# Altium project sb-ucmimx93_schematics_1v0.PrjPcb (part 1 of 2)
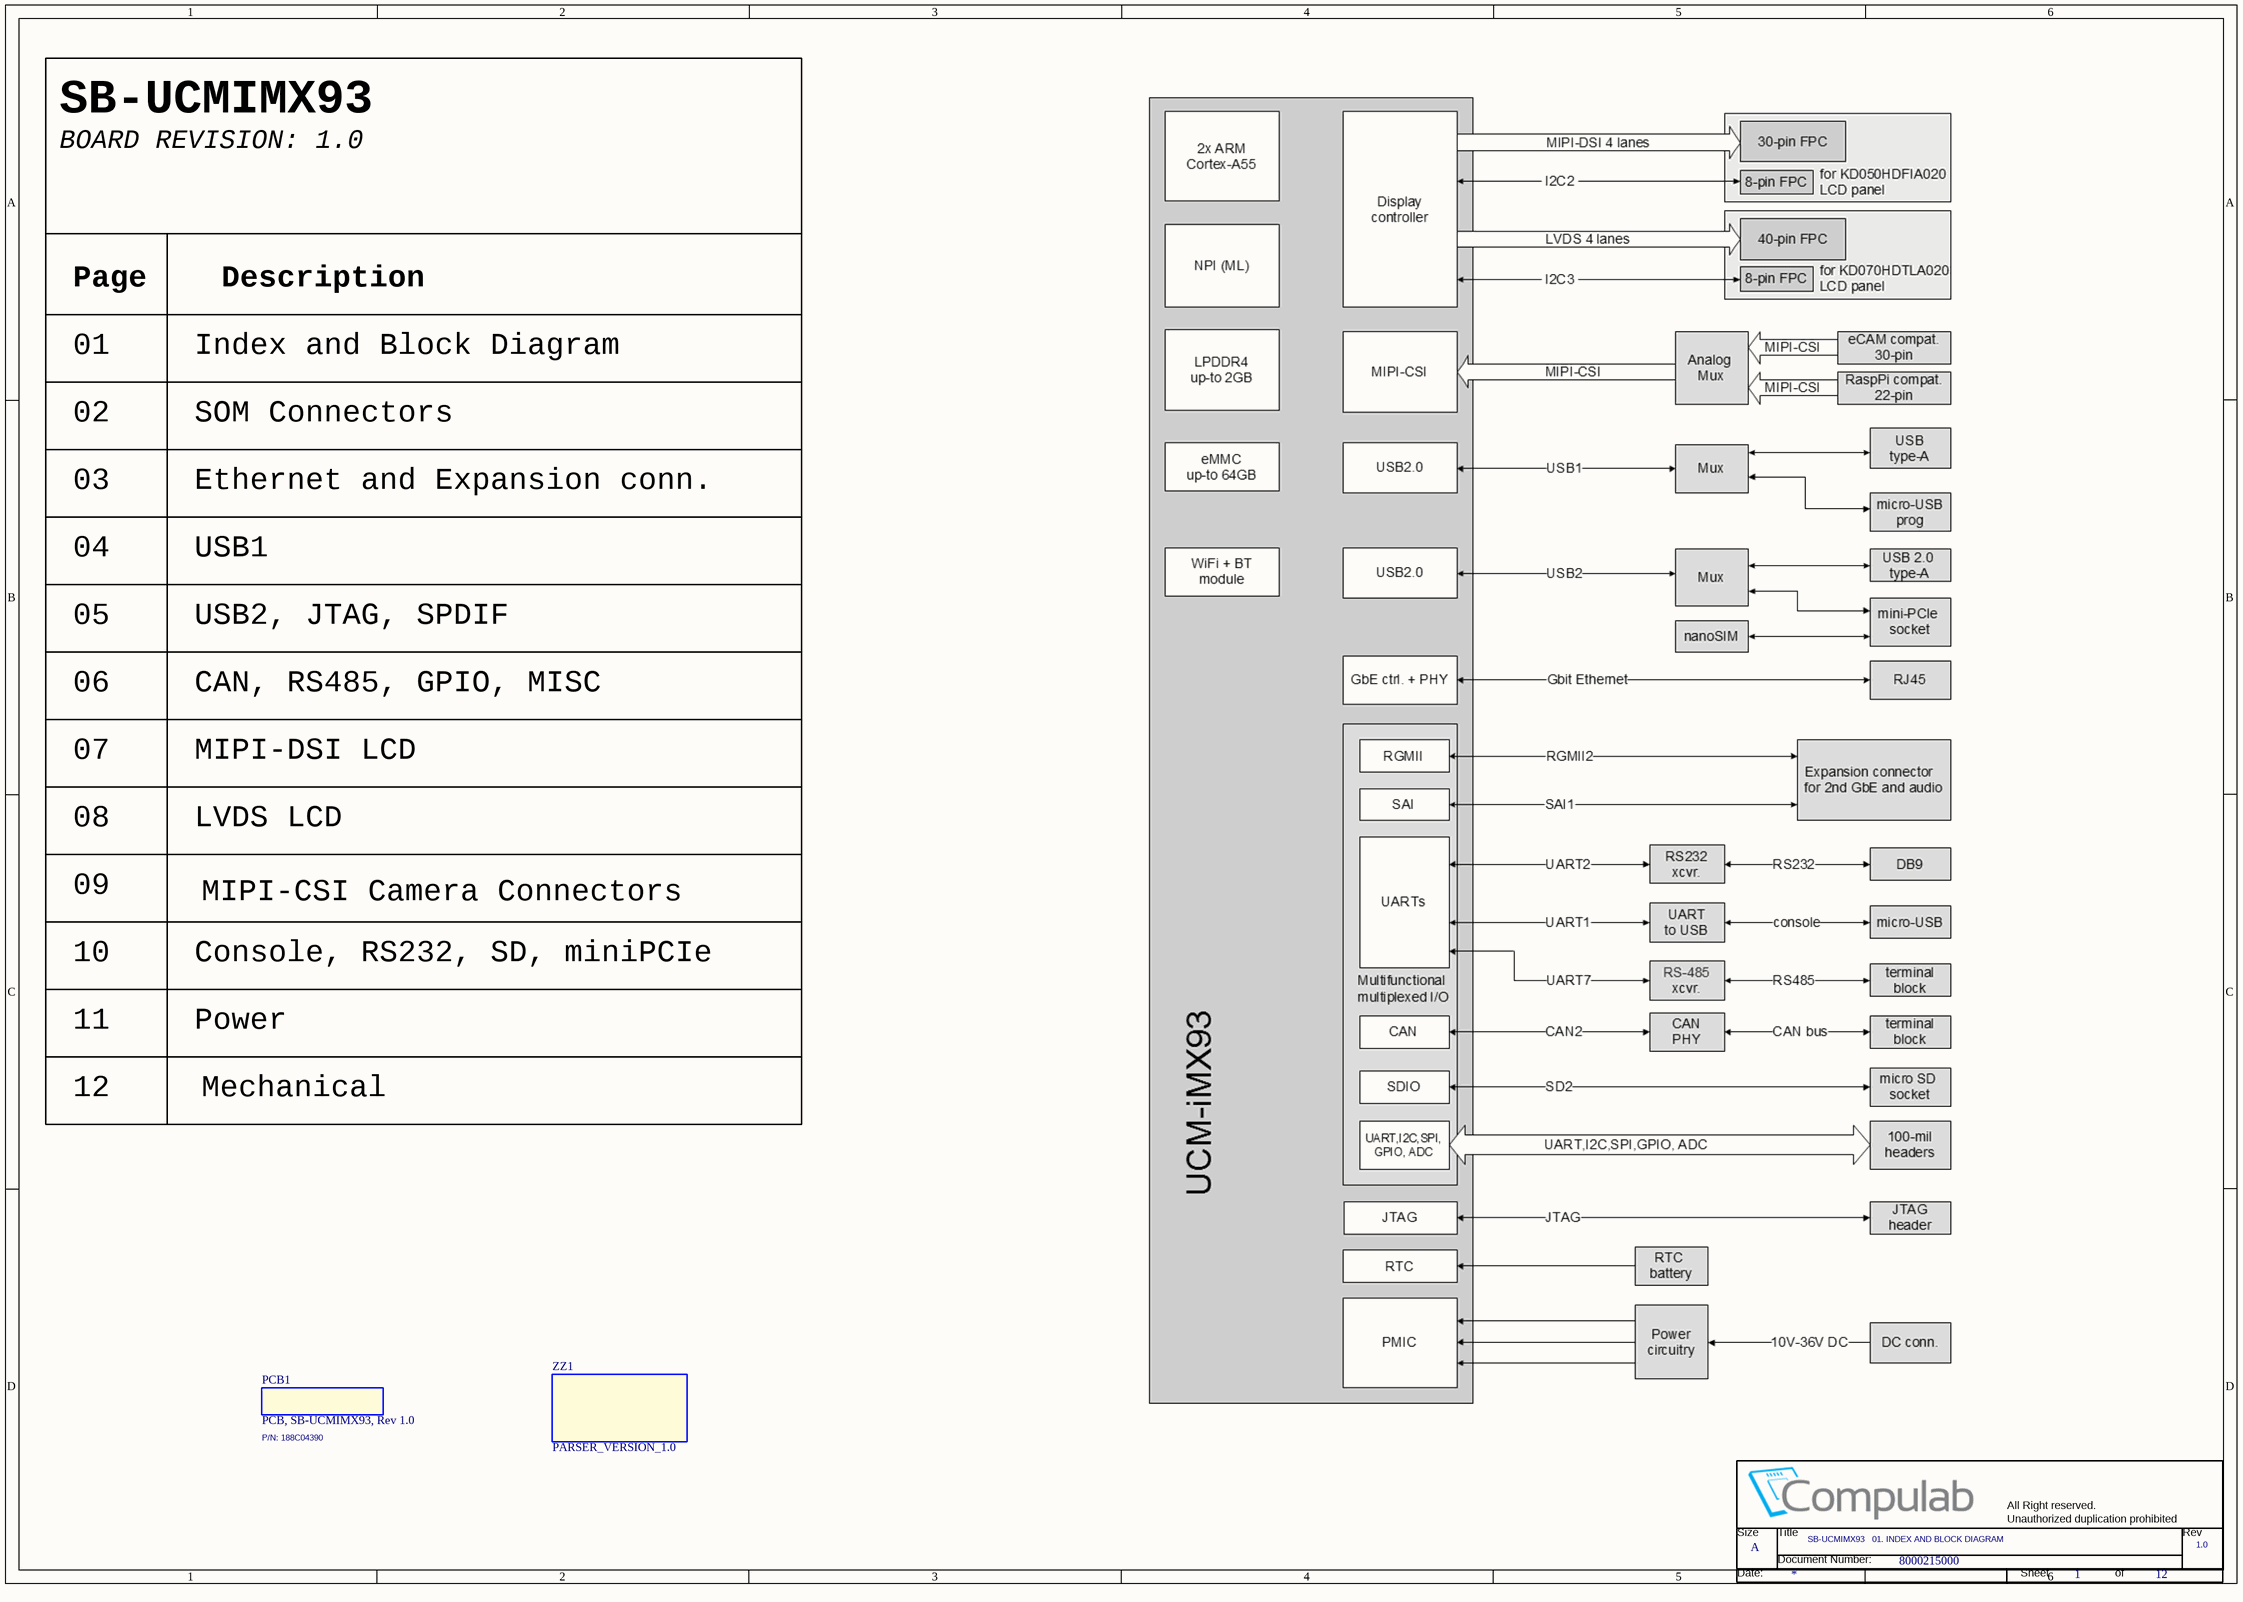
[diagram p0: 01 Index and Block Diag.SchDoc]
12 sheets, 492 parts. Net scope: flat (ports and power ports of the same name join across sheets).
Sheets:
  01 Index and Block Diag.SchDoc
  02 SOM Connectors.SchDoc
  03 Ethernet and Expansi.SchDoc
  04 USB1.SchDoc
  05 USB2, JTAG, SPDIF.SchDoc
  06 CAN, RS485, GPIO, MI.SchDoc
  07 MIPI-DSI LCD.SchDoc
  08 LVDS LCD.SchDoc
  09 MIPI-CSI Camera Conn.SchDoc
  10 Console, RS232, SD, .SchDoc
  11 Power.SchDoc
  12 Mechanical.SchDoc

## Sheet 01 Index and Block Diag.SchDoc
size 420 x 297 mm; DocumentNumber: 1; SheetNumber: 1; SheetTotal: 12

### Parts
(Parts that share a designator on the sheet are numbered #1, #2 ... from top to bottom, then left to right.)
*#1  Title: SB-UCMIMX93   01. INDEX AND BLOCK DIAGRAM  Doc: 8000215000  RevCode: 1.0  Page Size: A  Page Number: 1  Page Count: 12  (hidden comment: CompuLabTitleBlk)  (graphical)
PCB1  PCB, SB-UCMIMX93, Rev 1.0  P/N: 188C04390  [1X2THHDR]  (mechanical)
ZZ1  PARSER_VERSION_1.0  [1X2THHDR]  (mechanical)

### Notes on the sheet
- SB-UCMIMX93
- BOARD REVISION: 1.0
- Page
- Description
- 01
- Index and Block Diagram
- 02
- SOM Connectors
- 03
- Ethernet and Expansion conn.
- 04
- USB1
- 05
- USB2, JTAG, SPDIF
- 06
- CAN, RS485, GPIO, MISC
- 07
- MIPI-DSI LCD
- 08
- LVDS LCD
- 09
- MIPI-CSI Camera Connectors
- 10
- Console, RS232, SD, miniPCIe
- 11
- Power
- 12
- Mechanical

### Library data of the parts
PCB1 = PCB, EM-X270 Rev 1_0.1
ZZ1 = PARSER VERSION 1_1.0: P/N: 188Z10030; CLABCONF0: DNP

## Sheet 02 SOM Connectors.SchDoc
size 420 x 297 mm; DocumentNumber: 2; SheetNumber: 2; SheetTotal: 12
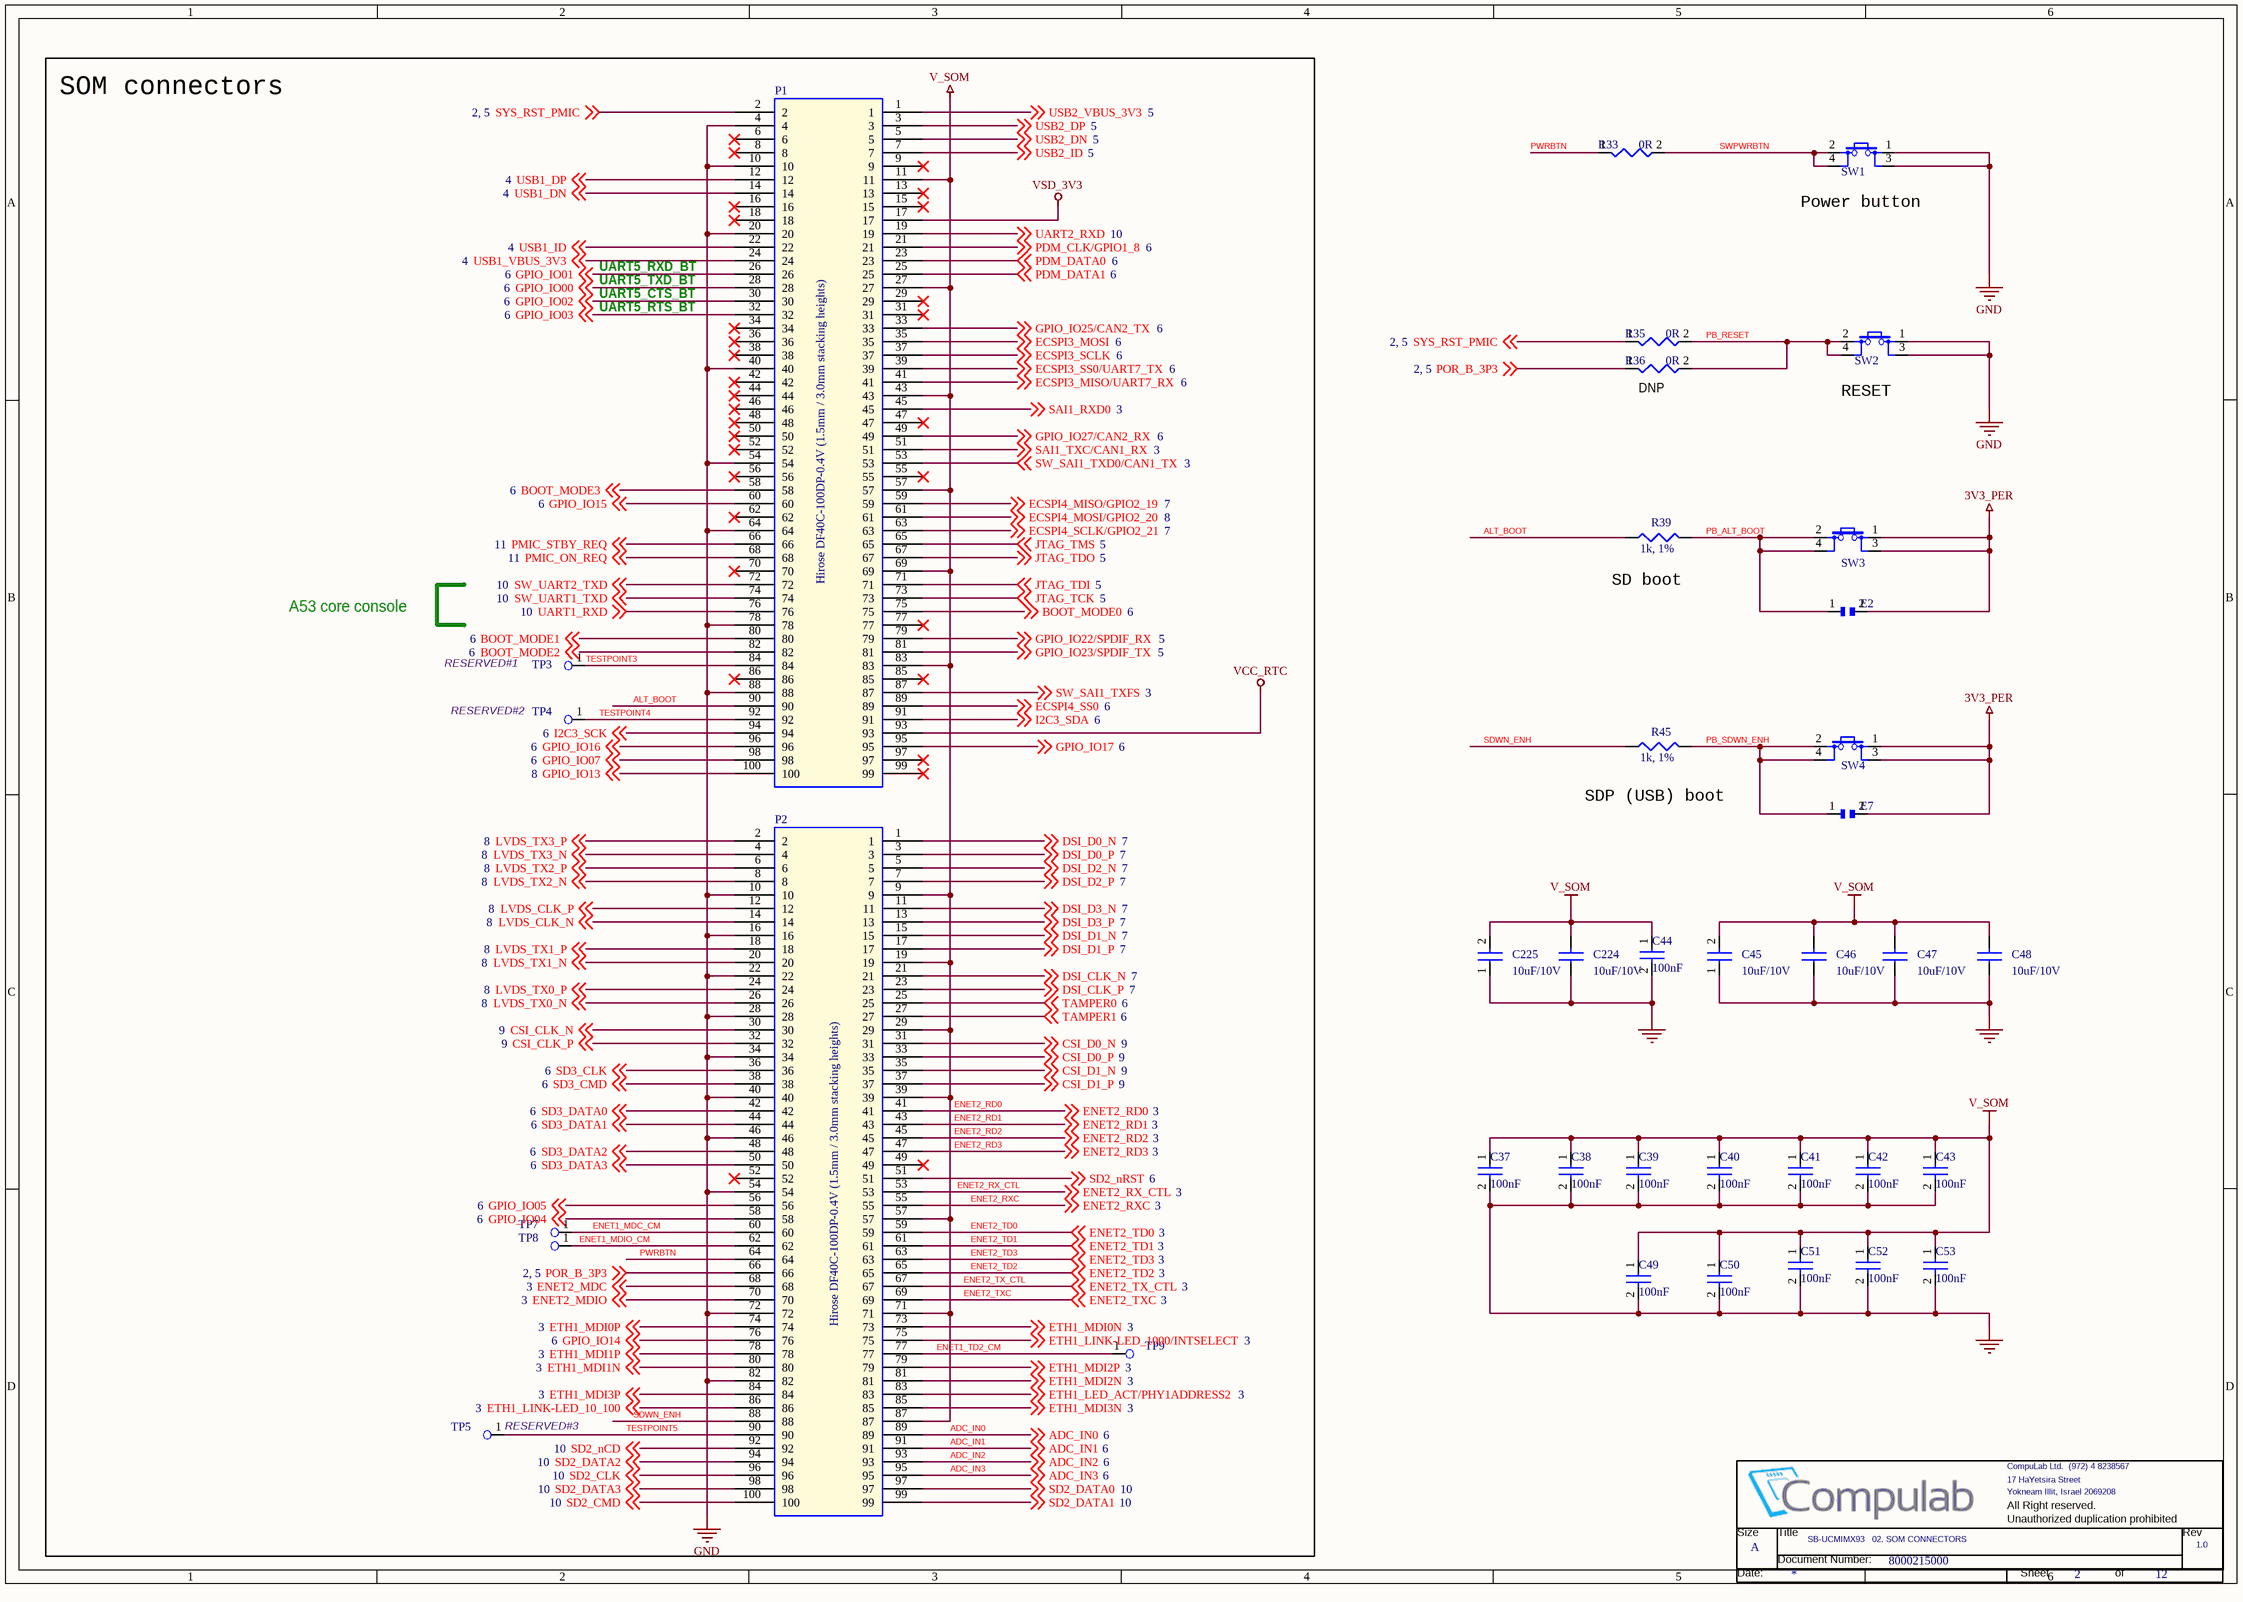
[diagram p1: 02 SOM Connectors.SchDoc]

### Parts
(Parts that share a designator on the sheet are numbered #1, #2 ... from top to bottom, then left to right.)
*#2  Title: SB-UCMIMX93   02. SOM CONNECTORS  Doc: 8000215000  RevCode: 1.0  OrgName: CompuLab Ltd.  (972) 4 8238567  OrgAddr1: 17 HaYetsira Street  OrgAddr2: Yokneam Illit, Israel 2069208  Page Size: A  Page Number: 2  Page Count: 12  (hidden comment: CompuLabTitleBlk)  (graphical)
C37  100nF  [RC0402]
C38  100nF  [RC0402]
C39  100nF  [RC0402]
C40  100nF  [RC0402]
C41  100nF  [RC0402]
C42  100nF  [RC0402]
C43  100nF  [RC0402]
C44  100nF  [RC0402]
C45  10uF/10V  [0402]
C46  10uF/10V  [0402]
C47  10uF/10V  [0402]
C48  10uF/10V  [0402]
C49  100nF  [RC0402]
C50  100nF  [RC0402]
C51  100nF  [RC0402]
C52  100nF  [RC0402]
C53  100nF  [RC0402]
C224  10uF/10V  [0402]
C225  10uF/10V  [0402]
E2  HDR1X2  [1X2THHDR]  (value not drawn)
E7  HDR1X2  [1X2THHDR]  (value not drawn)
P1  Hirose DF40C-100DP-0.4V (1.5mm / 3.0mm stacking heights)  [B2B04M2X50P]
P2  Hirose DF40C-100DP-0.4V (1.5mm / 3.0mm stacking heights)  [B2B04M2X50P]
R33  0R  [RC0402]
R35  0R  [RC0402]
R36  0R  [RC0402]
R39  1k, 1%  [RC0402]
R45  1k, 1%  [RC0402]
SW1  PushB  [TACTSW6x6SM]  (value not drawn)
SW2  PushB  [TACTSW6x6SM]  (value not drawn)
SW3  PushB  [TACTSW6x6SM]  (value not drawn)
SW4  PushB  [TACTSW6x6SM]  (value not drawn)
TP3  TESTPOINT SMT  [TESTPOINT]  (value not drawn)
TP4  TESTPOINT SMT  [TESTPOINT]  (value not drawn)
TP5  TESTPOINT SMT  [TESTPOINT]  (value not drawn)
TP7  TESTPOINT SMT  [TESTPOINT]  (value not drawn)
TP8  TESTPOINT SMT  [TESTPOINT]  (value not drawn)
TP9  TESTPOINT SMT  [TESTPOINT]  (value not drawn)

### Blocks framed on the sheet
SOM connectors: P1 P2 TP3-TP5 TP7-TP9

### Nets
3V3_PER: E2.2 E7.2 SW3.1 SW3.3 SW4.1 SW4.3
GND: C37.2 C38.2 C39.2 C40.2 C41.2 C42.2 C43.2 C44.2 C45.1 C46.1 C47.1 C48.1 C49.2 C50.2 C51.2 C52.2 C53.2 C224.1 C225.1 P1.4 P1.10 P1.20 P1.40 P1.54 P1.64 P1.78 P1.88 P2.10 P2.16 P2.22 P2.28 P2.34 P2.40 P2.46 P2.54 P2.72 P2.82 SW1.1 SW1.3 SW2.1 SW2.3
V_SOM: C37.1 C38.1 C39.1 C40.1 C41.1 C42.1 C43.1 C44.1 C45.2 C46.2 C47.2 C48.2 C49.1 C50.1 C51.1 C52.1 C53.1 C224.2 C225.2 P1.11 P1.27 P1.43 P1.57 P1.69 P1.83 P2.9 P2.19 P2.29 P2.39 P2.57 P2.71 P2.87
VCC_RTC: P1.93
VSD_3V3: P1.17
ADC_IN0: P2.89 ; off-sheet ADC_IN0
ADC_IN1: P2.91 ; off-sheet ADC_IN1
ADC_IN2: P2.93 ; off-sheet ADC_IN2
ADC_IN3: P2.95 ; off-sheet ADC_IN3
ALT_BOOT: P1.90 R39.1
BOOT_MODE0: P1.75 ; off-sheet BOOT_MODE0
BOOT_MODE1: P1.80 ; off-sheet BOOT_MODE1
BOOT_MODE2: P1.82 ; off-sheet BOOT_MODE2
BOOT_MODE3: P1.58 ; off-sheet BOOT_MODE3
CSI_CLK_N: P2.30 ; off-sheet CSI_CLK_N
CSI_CLK_P: P2.32 ; off-sheet CSI_CLK_P
CSI_D0_N: P2.31 ; off-sheet CSI_D0_N
CSI_D0_P: P2.33 ; off-sheet CSI_D0_P
CSI_D1_N: P2.35 ; off-sheet CSI_D1_N
CSI_D1_P: P2.37 ; off-sheet CSI_D1_P
DSI_CLK_N: P2.21 ; off-sheet DSI_CLK_N
DSI_CLK_P: P2.23 ; off-sheet DSI_CLK_P
DSI_D0_N: P2.1 ; off-sheet DSI_D0_N
DSI_D0_P: P2.3 ; off-sheet DSI_D0_P
DSI_D1_N: P2.15 ; off-sheet DSI_D1_N
DSI_D1_P: P2.17 ; off-sheet DSI_D1_P
DSI_D2_N: P2.5 ; off-sheet DSI_D2_N
DSI_D2_P: P2.7 ; off-sheet DSI_D2_P
DSI_D3_N: P2.11 ; off-sheet DSI_D3_N
DSI_D3_P: P2.13 ; off-sheet DSI_D3_P
ECSPI3_MISO/UART7_RX: P1.41 ; off-sheet ECSPI3_MISO/UART7_RX
ECSPI3_MOSI: P1.35 ; off-sheet ECSPI3_MOSI
ECSPI3_SCLK: P1.37 ; off-sheet ECSPI3_SCLK
ECSPI3_SS0/UART7_TX: P1.39 ; off-sheet ECSPI3_SS0/UART7_TX
ECSPI4_MISO/GPIO2_19: P1.59 ; off-sheet ECSPI4_MISO/GPIO2_19
ECSPI4_MOSI/GPIO2_20: P1.61 ; off-sheet ECSPI4_MOSI/GPIO2_20
ECSPI4_SCLK/GPIO2_21: P1.63 ; off-sheet ECSPI4_SCLK/GPIO2_21
ECSPI4_SS0: P1.89 ; off-sheet ECSPI4_SS0
ENET1_MDC_CM: P2.60 TP7.1
ENET1_MDIO_CM: P2.62 TP8.1
ENET1_TD2_CM: P2.77 TP9.1
ENET2_MDC: P2.68 ; off-sheet ENET2_MDC
ENET2_MDIO: P2.70 ; off-sheet ENET2_MDIO
ENET2_RD0: P2.41 ; off-sheet ENET2_RD0
ENET2_RD1: P2.43 ; off-sheet ENET2_RD1
ENET2_RD2: P2.45 ; off-sheet ENET2_RD2
ENET2_RD3: P2.47 ; off-sheet ENET2_RD3
ENET2_RX_CTL: P2.53 ; off-sheet ENET2_RX_CTL
ENET2_RXC: P2.55 ; off-sheet ENET2_RXC
ENET2_TD0: P2.59 ; off-sheet ENET2_TD0
ENET2_TD1: P2.61 ; off-sheet ENET2_TD1
ENET2_TD2: P2.65 ; off-sheet ENET2_TD2
ENET2_TD3: P2.63 ; off-sheet ENET2_TD3
ENET2_TX_CTL: P2.67 ; off-sheet ENET2_TX_CTL
ENET2_TXC: P2.69 ; off-sheet ENET2_TXC
ETH1_LED_ACT/PHY1ADDRESS2: P2.83 ; off-sheet ETH1_LED_ACT/PHY1ADDRESS2
ETH1_LINK-LED_10_100: P2.86 ; off-sheet ETH1_LINK-LED_10_100
ETH1_LINK-LED_1000/INTSELECT: P2.75 ; off-sheet ETH1_LINK-LED_1000/INTSELECT
ETH1_MDI0N: P2.73 ; off-sheet ETH1_MDI0N
ETH1_MDI0P: P2.74 ; off-sheet ETH1_MDI0P
ETH1_MDI1N: P2.80 ; off-sheet ETH1_MDI1N
ETH1_MDI1P: P2.78 ; off-sheet ETH1_MDI1P
ETH1_MDI2N: P2.81 ; off-sheet ETH1_MDI2N
ETH1_MDI2P: P2.79 ; off-sheet ETH1_MDI2P
ETH1_MDI3N: P2.85 ; off-sheet ETH1_MDI3N
ETH1_MDI3P: P2.84 ; off-sheet ETH1_MDI3P
GPIO_IO00: P1.28 ; off-sheet GPIO_IO00
GPIO_IO01: P1.26 ; off-sheet GPIO_IO01
GPIO_IO02: P1.30 ; off-sheet GPIO_IO02
GPIO_IO03: P1.32 ; off-sheet GPIO_IO03
GPIO_IO04: P2.58 ; off-sheet GPIO_IO04
GPIO_IO05: P2.56 ; off-sheet GPIO_IO05
GPIO_IO07: P1.98 ; off-sheet GPIO_IO07
GPIO_IO13: P1.100 ; off-sheet GPIO_IO13
GPIO_IO14: P2.76 ; off-sheet GPIO_IO14
GPIO_IO15: P1.60 ; off-sheet GPIO_IO15
GPIO_IO16: P1.96 ; off-sheet GPIO_IO16
GPIO_IO17: P1.95 ; off-sheet GPIO_IO17
GPIO_IO22/SPDIF_RX: P1.79 ; off-sheet GPIO_IO22/SPDIF_RX
GPIO_IO23/SPDIF_TX: P1.81 ; off-sheet GPIO_IO23/SPDIF_TX
GPIO_IO25/CAN2_TX: P1.33 ; off-sheet GPIO_IO25/CAN2_TX
GPIO_IO27/CAN2_RX: P1.49 ; off-sheet GPIO_IO27/CAN2_RX
I2C3_SCK: P1.94 ; off-sheet I2C3_SCK
I2C3_SDA: P1.91 ; off-sheet I2C3_SDA
JTAG_TCK: P1.73 ; off-sheet JTAG_TCK
JTAG_TDI: P1.71 ; off-sheet JTAG_TDI
JTAG_TDO: P1.67 ; off-sheet JTAG_TDO
JTAG_TMS: P1.65 ; off-sheet JTAG_TMS
LVDS_CLK_N: P2.14 ; off-sheet LVDS_CLK_N
LVDS_CLK_P: P2.12 ; off-sheet LVDS_CLK_P
LVDS_TX0_N: P2.26 ; off-sheet LVDS_TX0_N
LVDS_TX0_P: P2.24 ; off-sheet LVDS_TX0_P
LVDS_TX1_N: P2.20 ; off-sheet LVDS_TX1_N
LVDS_TX1_P: P2.18 ; off-sheet LVDS_TX1_P
LVDS_TX2_N: P2.8 ; off-sheet LVDS_TX2_N
LVDS_TX2_P: P2.6 ; off-sheet LVDS_TX2_P
LVDS_TX3_N: P2.4 ; off-sheet LVDS_TX3_N
LVDS_TX3_P: P2.2 ; off-sheet LVDS_TX3_P
PB_ALT_BOOT: E2.1 R39.2 SW3.2 SW3.4
PB_RESET: R35.2 R36.2 SW2.2 SW2.4
PB_SDWN_ENH: E7.1 R45.2 SW4.2 SW4.4
PDM_CLK/GPIO1_8: P1.21 ; off-sheet PDM_CLK/GPIO1_8
PDM_DATA0: P1.23 ; off-sheet PDM_DATA0
PDM_DATA1: P1.25 ; off-sheet PDM_DATA1
PMIC_ON_REQ: P1.68 ; off-sheet PMIC_ON_REQ
PMIC_STBY_REQ: P1.66 ; off-sheet PMIC_STBY_REQ
POR_B_3P3: P2.66 R36.1 ; off-sheet POR_B_3P3
PWRBTN: P2.64 R33.1
SAI1_RXD0: P1.45 ; off-sheet SAI1_RXD0
SAI1_TXC/CAN1_RX: P1.51 ; off-sheet SAI1_TXC/CAN1_RX
SD2_CLK: P2.96 ; off-sheet SD2_CLK
SD2_CMD: P2.100 ; off-sheet SD2_CMD
SD2_DATA0: P2.97 ; off-sheet SD2_DATA0
SD2_DATA1: P2.99 ; off-sheet SD2_DATA1
SD2_DATA2: P2.94 ; off-sheet SD2_DATA2
SD2_DATA3: P2.98 ; off-sheet SD2_DATA3
SD2_nCD: P2.92 ; off-sheet SD2_nCD
SD2_nRST: P2.51 ; off-sheet SD2_nRST
SD3_CLK: P2.36 ; off-sheet SD3_CLK
SD3_CMD: P2.38 ; off-sheet SD3_CMD
SD3_DATA0: P2.42 ; off-sheet SD3_DATA0
SD3_DATA1: P2.44 ; off-sheet SD3_DATA1
SD3_DATA2: P2.48 ; off-sheet SD3_DATA2
SD3_DATA3: P2.50 ; off-sheet SD3_DATA3
SDWN_ENH: P2.88 R45.1
SW_SAI1_TXD0/CAN1_TX: P1.53 ; off-sheet SW_SAI1_TXD0/CAN1_TX
SW_SAI1_TXFS: P1.87 ; off-sheet SW_SAI1_TXFS
SW_UART1_TXD: P1.74 ; off-sheet SW_UART1_TXD
SW_UART2_TXD: P1.72 ; off-sheet SW_UART2_TXD
SWPWRBTN: R33.2 SW1.2 SW1.4
SYS_RST_PMIC: P1.2 R35.1 ; off-sheet SYS_RST_PMIC
TAMPER0: P2.25 ; off-sheet TAMPER0
TAMPER1: P2.27 ; off-sheet TAMPER1
TESTPOINT3: P1.84 TP3.1
TESTPOINT4: P1.92 TP4.1
TESTPOINT5: P2.90 TP5.1
UART1_RXD: P1.76 ; off-sheet UART1_RXD
UART2_RXD: P1.19 ; off-sheet UART2_RXD
USB1_DN: P1.14 ; off-sheet USB1_DN
USB1_DP: P1.12 ; off-sheet USB1_DP
USB1_ID: P1.22 ; off-sheet USB1_ID
USB1_VBUS_3V3: P1.24 ; off-sheet USB1_VBUS_3V3
USB2_DN: P1.5 ; off-sheet USB2_DN
USB2_DP: P1.3 ; off-sheet USB2_DP
USB2_ID: P1.7 ; off-sheet USB2_ID
USB2_VBUS_3V3: P1.1 ; off-sheet USB2_VBUS_3V3

Not connected (* = marked no-connect by the designer): P1 6* 8* 9* 13* 15* 16* 18* 29* 31* 34* 36* 38* 42* 44* 46* 47* 48* 50* 52* 55* 56* 62* 70* 77* 85* 86* 97* 99*; P2 49* 52*

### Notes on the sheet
- (near SW1) Power button
- UART5_RXD_BT
- UART5_TXD_BT
- UART5_CTS_BT
- UART5_RTS_BT
- (near R36) DNP
- (near SW2) RESET
- (near R39) SD boot
- A53 core console
- RESERVED#1
- RESERVED#2
- (near R45) SDP (USB) boot
- (near TP5) RESERVED#3

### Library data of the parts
C37-C44 C49-C53 = 100nF, 10V, X7R, 10%, 0402_Dup1: P/N: 151B10400S
C45 C225 = 10uF 10V 20% 0402: OriginalSymbolOrigin: (0,0); P/N: 151B10600S
C46-C48 C224 = 10uF,6.3V,0603,20%X5R: P/N: 151B10600S
E2 E7 = HDR 1x2 100MIL TH JUMPER: P/N: 190C00200
P1 = Hirose DF40C-100DP-0_0.4V: P/N: 182K10004S
P2 = Hirose DF40C-100DP-0_1.4V: P/N: 182K10004S
R33 R35 = 0R, 0402_0: P/N: 161C00005S
R36 = 0R, 0402_0: P/N: 161C00005S; CLABCONF0: DNP
R39 R45 = RESISTOR: P/N: 161C10011S
SW1-SW4 = TACT SW 6x6mm SMT: P/N: 170B00001S
TP3 TP8 = TESTPOINT: CLABCONF0: DNP; P/N: 188Z01370S
TP4 TP5 TP7 TP9 = TESTPOINT: P/N: 188Z01370S; CLABCONF0: DNP

## Sheet 03 Ethernet and Expansi.SchDoc
size 420 x 297 mm; DocumentNumber: 3; SheetNumber: 3; SheetTotal: 12
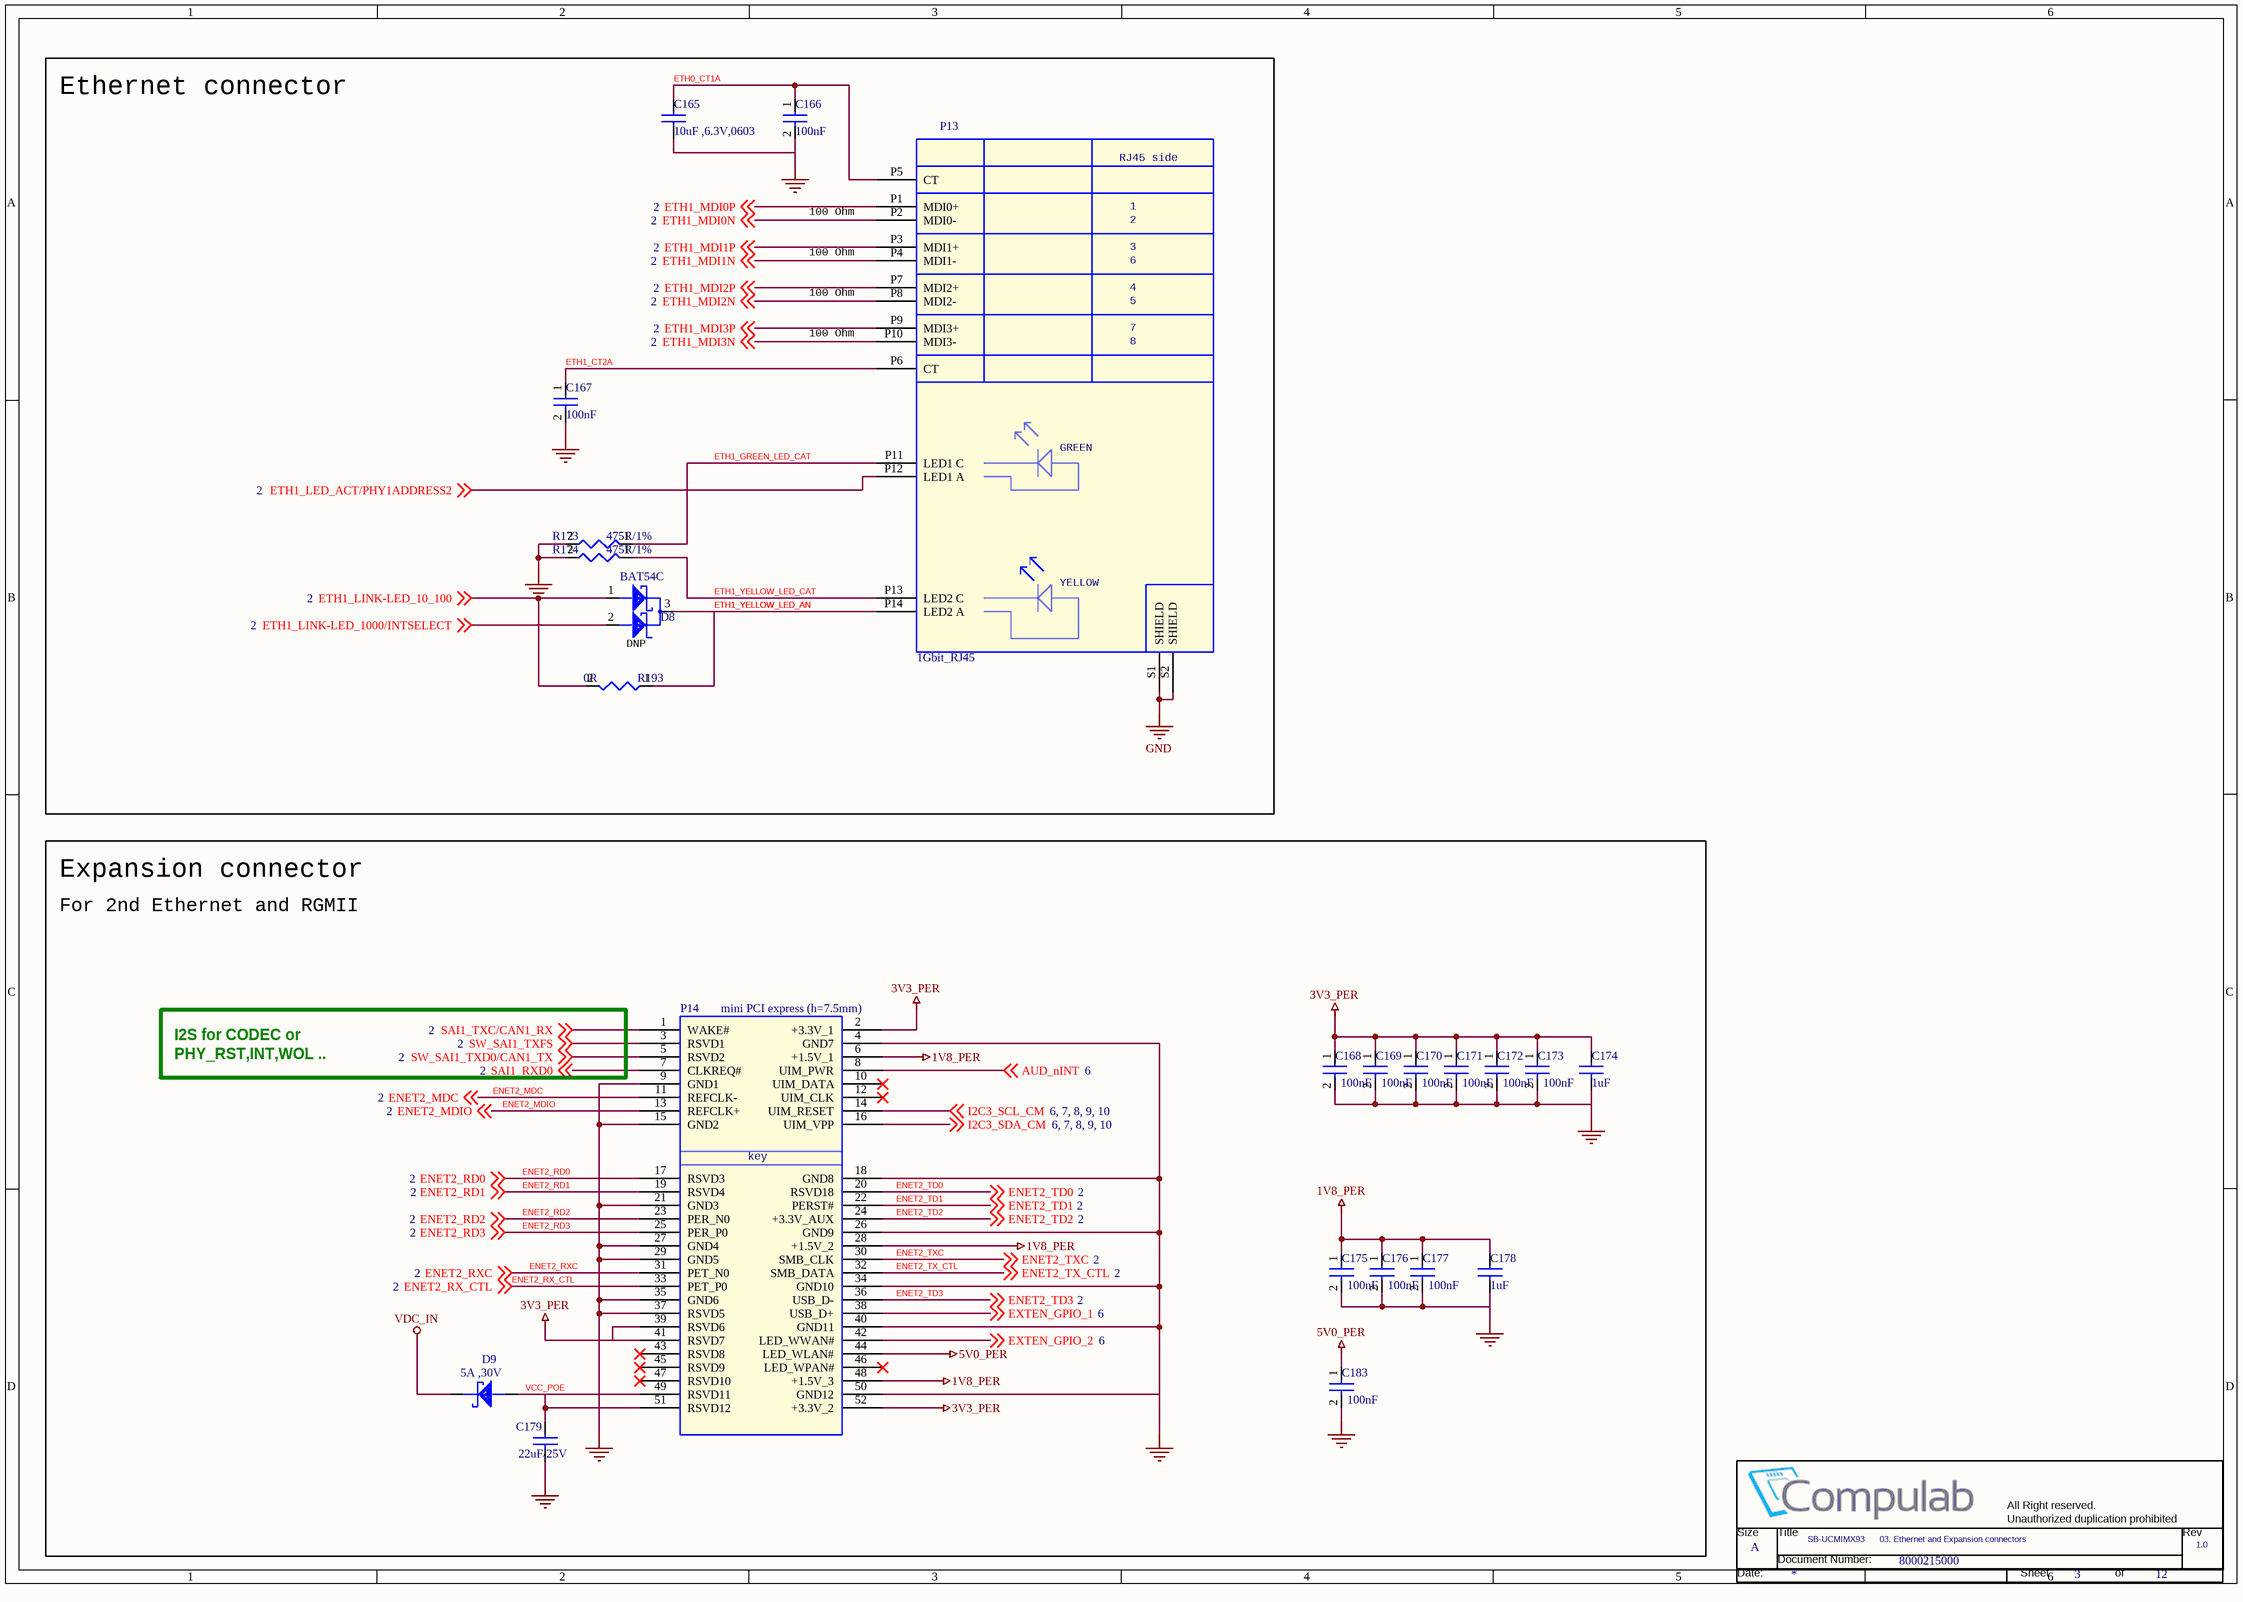
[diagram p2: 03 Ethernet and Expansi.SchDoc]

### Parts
(Parts that share a designator on the sheet are numbered #1, #2 ... from top to bottom, then left to right.)
*#3  Title: SB-UCMIMX93      03. Ethernet and Expansion connectors  Doc: 8000215000  RevCode: 1.0  Page Size: A  Page Number: 3  Page Count: 12  (hidden comment: CompuLabTitleBlk)  (graphical)
C165  10uF ,6.3V,0603  [RC0603]
C166  100nF  [RC0402]
C167  100nF  [RC0402]
C168  100nF  [RC0402]
C169  100nF  [RC0402]
C170  100nF  [RC0402]
C171  100nF  [RC0402]
C172  100nF  [RC0402]
C173  100nF  [RC0402]
C174  1uF  [RC0402]
C175  100nF  [RC0402]
C176  100nF  [RC0402]
C177  100nF  [RC0402]
C178  1uF  [RC0402]
C179  22uF/25V  [C0805]
C183  100nF  [RC0402]
D8  BAT54C  [SOT23]
D9  5A ,30V  [SOD-128]
P13  1Gbit_RJ45  [DUSBRJ-1G]
P14  mini PCI express (h=7.5mm)  [MINIPCIE-4]
R173  475R/1%  [RC0402]
R174  475R/1%  [RC0402]
R193  0R  [RC0402]

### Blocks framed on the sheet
Ethernet connector: C165-C167 D8 P13 R173 R174 R193
Expansion connector: C168-C179 C183 D9 P14

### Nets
1V8_PER: C175.1 C176.1 C177.1 C178.1 P14.6(+1.5V_1) P14.28(+1.5V_2) P14.48(+1.5V_3)
3V3_PER: C168.1 C169.1 C170.1 C171.1 C172.1 C173.1 C174.1 P14.2(+3.3V_1) P14.39(RSVD6) P14.41(RSVD7) P14.52(+3.3V_2)
5V0_PER: C183.1 P14.44(LED_WLAN#)
GND: C165.2 C166.2 C167.2 C168.2 C169.2 C170.2 C171.2 C172.2 C173.2 C174.2 C175.2 C176.2 C177.2 C178.2 C179.2 C183.2 P13.S1(SHIELD) P13.S2(SHIELD) P14.4(GND7) P14.9(GND1) P14.15(GND2) P14.18(GND8) P14.21(GND3) P14.26(GND9) P14.27(GND4) P14.29(GND5) P14.34(GND10) P14.35(GND6) P14.37(RSVD5) P14.40(GND11) P14.50(GND12) R173.2 R174.2
VDC_IN: D9.CATHODE
AUD_nINT: P14.8(UIM_PWR) ; off-sheet AUD_nINT
ENET2_MDC: P14.11(REFCLK-) ; off-sheet ENET2_MDC
ENET2_MDIO: P14.13(REFCLK+) ; off-sheet ENET2_MDIO
ENET2_RD0: P14.17(RSVD3) ; off-sheet ENET2_RD0
ENET2_RD1: P14.19(RSVD4) ; off-sheet ENET2_RD1
ENET2_RD2: P14.23(PER_N0) ; off-sheet ENET2_RD2
ENET2_RD3: P14.25(PER_P0) ; off-sheet ENET2_RD3
ENET2_RX_CTL: P14.33(PET_P0) ; off-sheet ENET2_RX_CTL
ENET2_RXC: P14.31(PET_N0) ; off-sheet ENET2_RXC
ENET2_TD0: P14.20(RSVD18) ; off-sheet ENET2_TD0
ENET2_TD1: P14.22(PERST#) ; off-sheet ENET2_TD1
ENET2_TD2: P14.24(+3.3V_AUX) ; off-sheet ENET2_TD2
ENET2_TD3: P14.36(USB_D-) ; off-sheet ENET2_TD3
ENET2_TX_CTL: P14.32(SMB_DATA) ; off-sheet ENET2_TX_CTL
ENET2_TXC: P14.30(SMB_CLK) ; off-sheet ENET2_TXC
ETH0_CT1A: C165.1 C166.1 P13.P5(CT)
ETH1_CT2A: C167.1 P13.P6(CT)
ETH1_GREEN_LED_CAT: P13.P11(LED1_C) R173.1
ETH1_LED_ACT/PHY1ADDRESS2: P13.P12(LED1_A) ; off-sheet ETH1_LED_ACT/PHY1ADDRESS2
ETH1_LINK-LED_10_100: D8.1(ANODE1) R193.2 ; off-sheet ETH1_LINK-LED_10_100
ETH1_LINK-LED_1000/INTSELECT: D8.2(ANODE2) ; off-sheet ETH1_LINK-LED_1000/INTSELECT
ETH1_MDI0N: P13.P2(MDI0-) ; off-sheet ETH1_MDI0N
ETH1_MDI0P: P13.P1(MDI0+) ; off-sheet ETH1_MDI0P
ETH1_MDI1N: P13.P4(MDI1-) ; off-sheet ETH1_MDI1N
ETH1_MDI1P: P13.P3(MDI1+) ; off-sheet ETH1_MDI1P
ETH1_MDI2N: P13.P8(MDI2-) ; off-sheet ETH1_MDI2N
ETH1_MDI2P: P13.P7(MDI2+) ; off-sheet ETH1_MDI2P
ETH1_MDI3N: P13.P10(MDI3-) ; off-sheet ETH1_MDI3N
ETH1_MDI3P: P13.P9(MDI3+) ; off-sheet ETH1_MDI3P
ETH1_YELLOW_LED_AN: D8.3(CATHODE) P13.P14(LED2_A) R193.1
ETH1_YELLOW_LED_CAT: P13.P13(LED2_C) R174.1
EXTEN_GPIO_1: P14.38(USB_D+) ; off-sheet EXTEN_GPIO_1
EXTEN_GPIO_2: P14.42(LED_WWAN#) ; off-sheet EXTEN_GPIO_2
I2C3_SCL_CM: P14.14(UIM_RESET) ; off-sheet I2C3_SCL_CM
I2C3_SDA_CM: P14.16(UIM_VPP) ; off-sheet I2C3_SDA_CM
SAI1_RXD0: P14.7(CLKREQ#) ; off-sheet SAI1_RXD0
SAI1_TXC/CAN1_RX: P14.1(WAKE#) ; off-sheet SAI1_TXC/CAN1_RX
SW_SAI1_TXD0/CAN1_TX: P14.5(RSVD2) ; off-sheet SW_SAI1_TXD0/CAN1_TX
SW_SAI1_TXFS: P14.3(RSVD1) ; off-sheet SW_SAI1_TXFS
VCC_POE: C179.1 D9.ANODE P14.49(RSVD11) P14.51(RSVD12)

Not connected (* = marked no-connect by the designer): P14 10(UIM_DATA)* 12(UIM_CLK)* 43(RSVD8)* 45(RSVD9)* 46(LED_WPAN#)* 47(RSVD10)*

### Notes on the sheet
- 100 Ohm
- (near D8) DNP
- For 2nd Ethernet and RGMII
- I2S for CODEC or
  PHY_RST,INT,WOL ..

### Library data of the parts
C165 = Cap.,10uF,6.3V,0603,X5R: P/N: 151B10610S
C166-C173 C175-C177 C183 = 100nF, 10V, X7R, 10%, 0402_Dup1: P/N: 151B10400S
C174 C178 = 1uF,X5R,6.3V,0402: P/N: 151B10500S
C179 = Cap.,22uF,25V, 0805: P/N: 151C22620S
D8 = BAT54C: P/N: 130E05400S; CLABCONF0: DNP
D9 = Diode Shotky,5A,30V: P/N: 130E30001S
P13 = Con_0.,1GBit RJ45, short: P/N: 182K01600
P14 = mini PCIe_0: P/N: 182K05202S
R173 R174 = 475R/1%, 0402: P/N: 161C47501S
R193 = 0R, 0402_1: P/N: 161C00005S

## Sheet 04 USB1.SchDoc
size 420 x 297 mm; DocumentNumber: 4; SheetNumber: 4; SheetTotal: 12
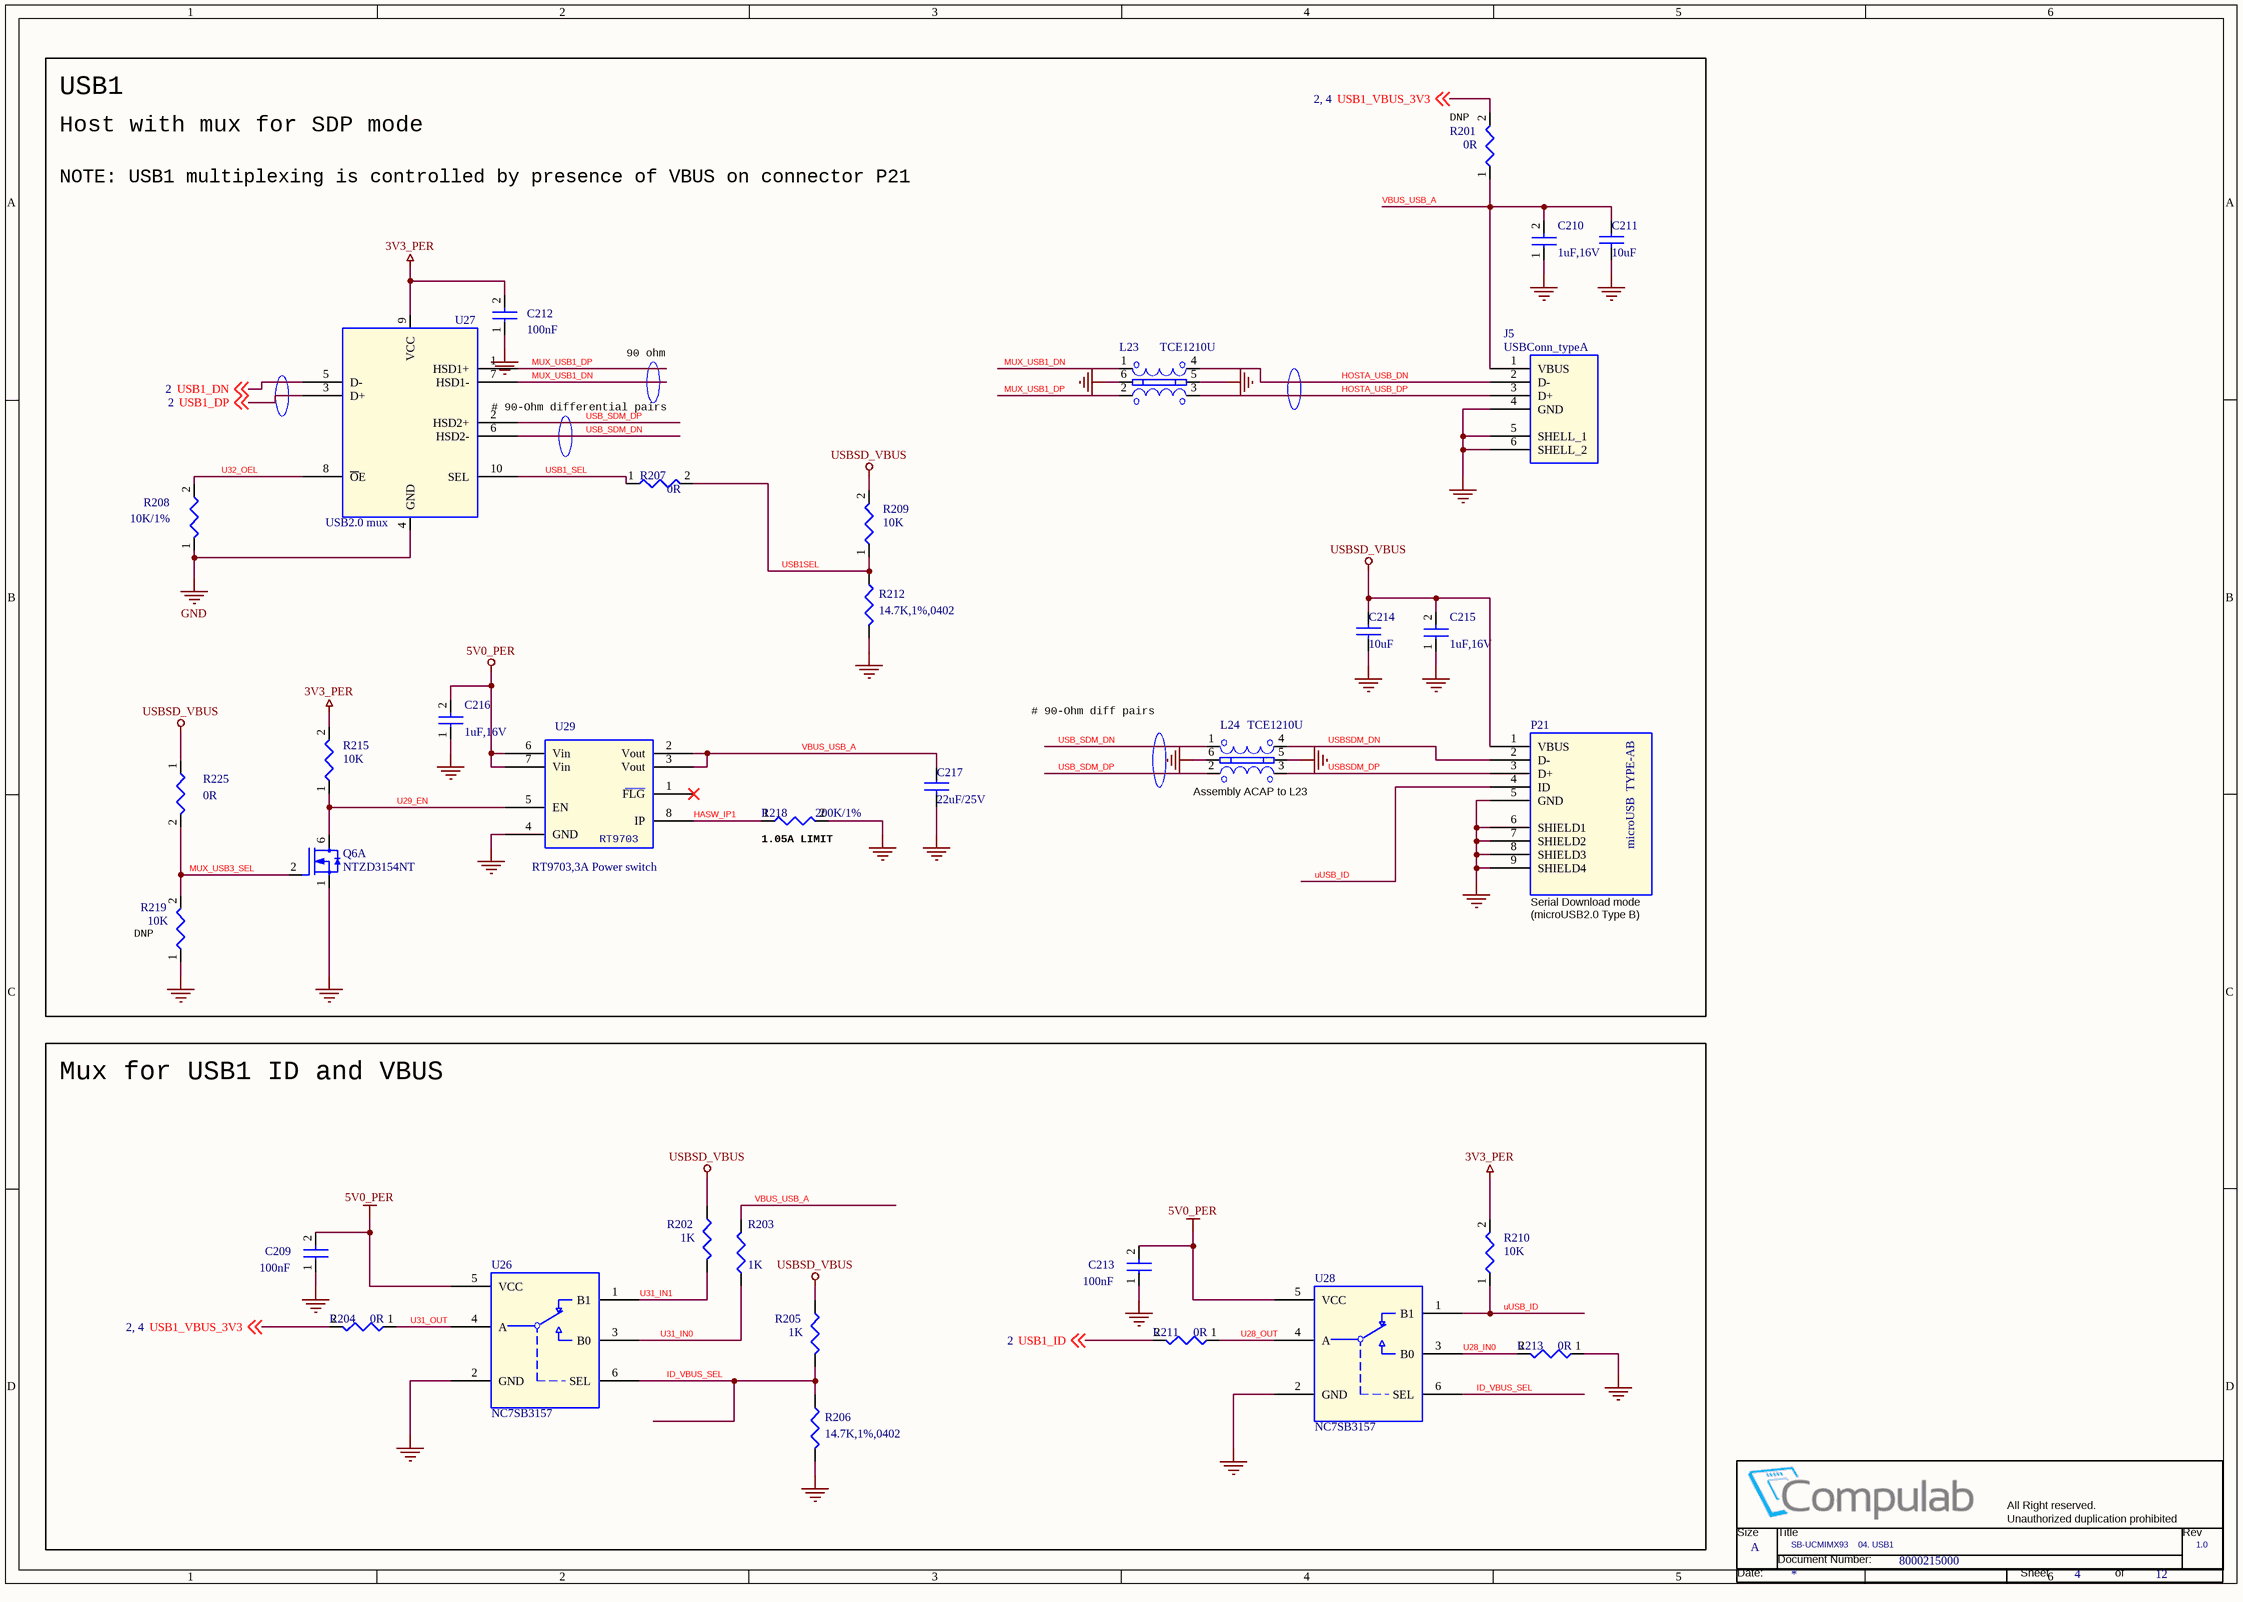
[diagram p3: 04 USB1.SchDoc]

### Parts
(Parts that share a designator on the sheet are numbered #1, #2 ... from top to bottom, then left to right.)
*#4  Title: SB-UCMIMX93    04. USB1  Doc: 8000215000  RevCode: 1.0  Page Size: A  Page Number: 4  Page Count: 12  (hidden comment: CompuLabTitleBlk)  (graphical)
C209  100nF  [RC0402]
C210  1uF,16V  [RC0402]
C211  10uF  [C0603-08]
C212  100nF  [RC0402]
C213  100nF  [RC0402]
C214  10uF  [C0603-08]
C215  1uF,16V  [RC0402]
C216  1uF,16V  [RC0402]
C217  22uF/25V  [C0805]
J5  USBConn_typeA  [USB-A-SM]
L23  TCE1210U  [EMI1012-ESD]
L24  TCE1210U  [EMI1012-ESD]
P21  microUSB  TYPE-AB  [MICRO-USB-AB-RA-SM]
Q6  NTZD3154NT  [SOT-563-6]  (part A of 2)
R201  0R  [RC0402]
R202  1K  [RC0402]
R203  1K  [RC0402]
R204  0R  [RC0402]
R205  1K  [RC0402]
R206  14.7K,1%,0402  [RC0402]
R207  0R  [RC0402]
R208  10K/1%  [RC0402]
R209  10K  [RC0402]
R210  10K  [RC0402]
R211  0R  [RC0402]
R212  14.7K,1%,0402  [RC0402]
R213  0R  [RC0402]
R215  10K  [RC0402]
R218  200K/1%  [RC0402]
R219  10K  [RC0402]
R225  0R  [RC0402]
U26  NC7SB3157  [SC70-6]
U27  USB2.0 mux  [MO-255U1418E]
U28  NC7SB3157  [SC70-6]
U29  RT9703,3A Power switch  [SO8-150]

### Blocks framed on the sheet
USB1: C210-C212 C214-C217 J5 L23 L24 P21 Q6 R201 R207-R209 R212 R215 R218 R219 R225 U27 U29
Mux for USB1 ID and VBUS: C209 C213 R202-R206 R210 R211 R213 U26 U28

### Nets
3V3_PER: C212.2 R210.2 R215.2 U27.9(VCC)
5V0_PER: C209.2 C213.2 C216.2 U26.5(VCC) U28.5(VCC) U29.6(Vin) U29.7(Vin)
GND: C209.1 C210.1 C211.2 C212.1 C213.1 C214.2 C215.1 C216.1 C217.2 J5.4(GND) J5.5(SHELL_1) J5.6(SHELL_2) L23.5(GND) L23.6(GND) L24.5(GND) L24.6(GND) P21.5(GND) P21.6(SHIELD1) P21.7(SHIELD2) P21.8(SHIELD3) P21.9(SHIELD4) Q6.1(S) R206.2 R208.1 R212.2 R213.1 R218.2 R219.1 U26.2(GND) U27.4(GND) U28.2(GND) U29.4(GND)
USBSD_VBUS: C214.1 C215.2 P21.1(VBUS) R202.1 R205.1 R209.2 R225.1
HASW_IP1: R218.1 U29.8(IP)
HOSTA_USB_DN: J5.2(D-) L23.4
HOSTA_USB_DP: J5.3(D+) L23.3
ID_VBUS_SEL: R205.2 R206.1 U26.6(SEL) U28.6(SEL)
MUX_USB1_DN: L23.1 U27.7(HSD1-)
MUX_USB1_DP: L23.2 U27.1(HSD1+)
MUX_USB3_SEL: Q6.2(G) R219.2 R225.2
U28_IN0: R213.2 U28.3(B0)
U28_OUT: R211.1 U28.4(A)
U29_EN: Q6.6(D) R215.1 U29.5(EN)
U31_IN0: R203.2 U26.3(B0)
U31_IN1: R202.2 U26.1(B1)
U31_OUT: R204.1 U26.4(A)
U32_OEL: R208.2 U27.8(~{O}E)
USB1_DN: U27.5(D-) ; off-sheet USB1_DN
USB1_DP: U27.3(D+) ; off-sheet USB1_DP
USB1_ID: R211.2 ; off-sheet USB1_ID
USB1_SEL: R207.1 U27.10(SEL)
USB1_VBUS_3V3: R201.2 R204.2 ; off-sheet USB1_VBUS_3V3
USB1SEL: R207.2 R209.1 R212.1
USB_SDM_DN: L24.1 U27.6(HSD2-)
USB_SDM_DP: L24.2 U27.2(HSD2+)
USBSDM_DN: L24.4 P21.2(D-)
USBSDM_DP: L24.3 P21.3(D+)
uUSB_ID: P21.4(ID) R210.1 U28.1(B1)
VBUS_USB_A: C210.2 C211.1 C217.1 J5.1(VBUS) R201.1 R203.1 U29.2(Vout) U29.3(Vout)

Not connected (* = marked no-connect by the designer): U29 1(FLG)*

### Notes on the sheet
- (near R201) DNP
- Host with mux for SDP mode
- NOTE: USB1 multiplexing is controlled by presence of VBUS on connector P21
- 90 ohm
- (near U27) # 90-Ohm differential pairs
- # 90-Ohm diff pairs
- (near L24) Assembly ACAP to L23
- (near R218) 1.05A LIMIT
- (near R219) DNP
- (near P21) Serial Download mode
  (microUSB2.0 Type B)

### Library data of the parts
C209 C212 C213 = 100nF, 10V, X7R, 10%, 0402_Dup1: P/N: 151B10400S; Group: LAN2
C210 C215 C216 = 100nF, 10V, X7R, 10%, 0402: P/N: 151C10500S
C211 C214 = 10uF,6_0.3V,0603,20%X5R: P/N: 151B10610S
C217 = 22uF,25V, 0805: P/N: 151C22620S
J5 = USB Conn., Fem, Type A , TH, RA: P/N: 180K00400S
L23 L24 = ESD_CHOKE_DIFFx2_10: P/N: 142D11801S
P21 = Conn., Micro-USB, B-Type: P/N: 180K00501S
Q6 = N-MOSFET_Dual: P/N: 131D31540S
R201 = 0R, 0402: P/N: 161C00005S; CLABCONF0: DNP
R202 R203 R205 = RESISTOR_Dup1: P/N: 161C10011S
R204 R207 R211 R213 R225 = 0R, 0402: P/N: 161C00005S
R206 R212 = RESISTOR_Dup1: P/N: 161C14721S
R208 = 10K,1%,0402,1/16W_0_Dup1: P/N: 161C10021S
R209 R210 R215 = 1M ,5%, 0402: P/N: 161C10021S
R218 = 100K, 1%, 0402, 1/16W: P/N: 161C20031S
R219 = 1M ,5%, 0402: P/N: 161C10021S; CLABCONF0: DNP
U26 U28 = Bus switch 2:1: P/N: 124S10050S
U27 = USB2_0.0 mux: P/N: 116A72220S
U29 = RT9703,3A Power switch+FLG: P/N: 124S10080S

## Sheet 05 USB2, JTAG, SPDIF.SchDoc
size 420 x 297 mm; DocumentNumber: 5; SheetNumber: 5; SheetTotal: 12
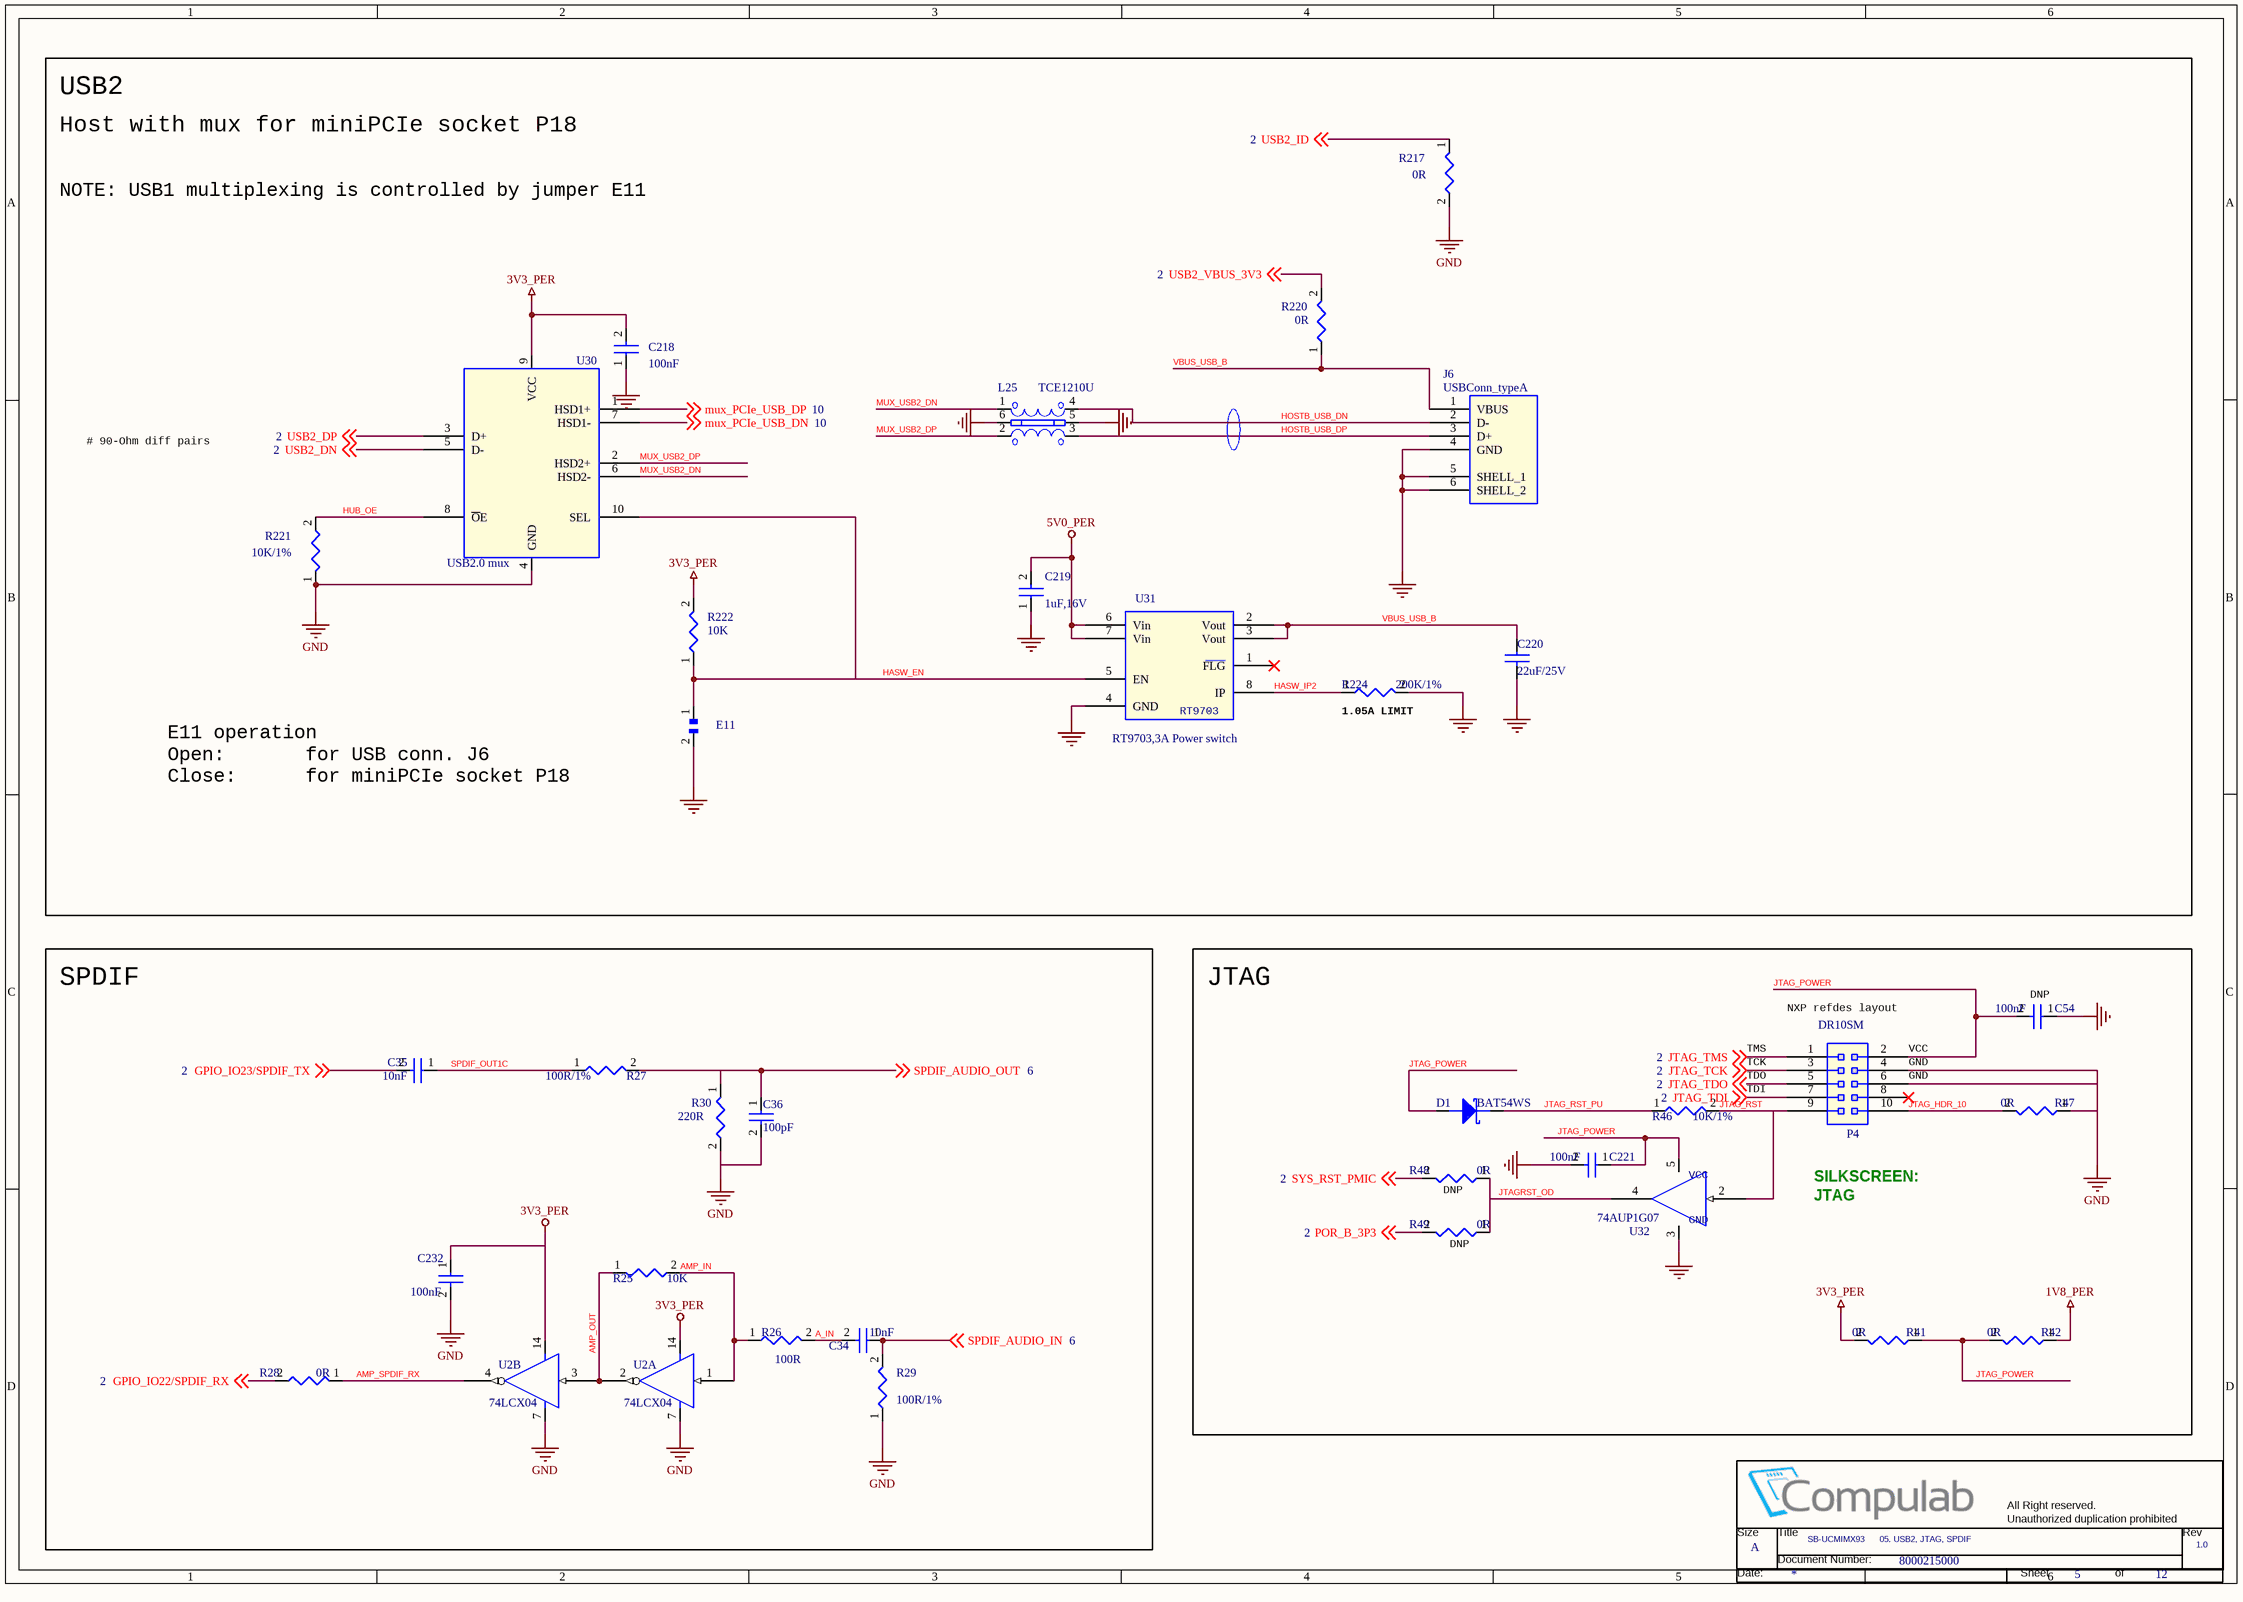
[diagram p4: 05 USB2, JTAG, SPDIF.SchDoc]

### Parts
(Parts that share a designator on the sheet are numbered #1, #2 ... from top to bottom, then left to right.)
*#5  Title: SB-UCMIMX93      05. USB2, JTAG, SPDIF  Doc: 8000215000  RevCode: 1.0  Page Size: A  Page Number: 5  Page Count: 12  (hidden comment: CompuLabTitleBlk)  (graphical)
C34  10nF  [RC0402]
C35  10nF  [RC0402]
C36  100pF  [RC0402]
C54  100nF  [RC0402]
C218  100nF  [RC0402]
C219  1uF,16V  [RC0402]
C220  22uF/25V  [C0805]
C221  100nF  [RC0402]
C232  100nF  [RC0402]
D1  BAT54WS  [SOD-323]
E11  HDR1X2  [1X2THHDR]  (value not drawn)
J6  USBConn_typeA  [USB-A-SM]
L25  TCE1210U  [EMI1012-ESD]
P4  DR10SM  [2X5SMHDR]
R25  10K  [RC0402]
R26  100R  [RC0402]
R27  100R/1%  [RC0402]
R28  0R  [RC0402]
R29  100R/1%  [RC0402]
R30  220R  [RC0402]
R41  0R  [RC0402]
R42  0R  [RC0402]
R46  10K/1%  [RC0402]
R47  0R  [RC0402]
R48  0R  [RC0402]
R49  0R  [RC0402]
R217  0R  [RC0402]
R220  0R  [RC0402]
R221  10K/1%  [RC0402]
R222  10K  [RC0402]
R224  200K/1%  [RC0402]
U2  74LCX04  [TSSOP-14]  (parts A,B of 6)
U30  USB2.0 mux  [MO-255U1418E]
U31  RT9703,3A Power switch  [SO8-150]
U32  74AUP1G07  [SC70]

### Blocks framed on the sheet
USB2: C218-C220 E11 J6 L25 R217 R220-R222 R224 U30 U31
SPDIF: C34-C36 C232 R25-R30 U2
JTAG: C54 C221 D1 P4 R41 R42 R46-R49 U32

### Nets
1V8_PER: R42.1
3V3_PER: C218.2 C232.1 R41.2 R222.2 U2.14(VCC) U30.9(VCC)
5V0_PER: C219.2 U31.6(Vin) U31.7(Vin)
GND: C36.2 C54.1 C218.1 C219.1 C220.2 C221.2 C232.2 E11.2 J6.4(GND) J6.5(SHELL_1) J6.6(SHELL_2) L25.5(GND) L25.6(GND) P4.4 P4.6 R29.1 R30.2 R47.1 R217.2 R221.1 R224.2 U2.7(GND) U30.4(GND) U31.4(GND) U32.3(GND)
A_IN: C34.2 R26.2
AMP_IN: R25.2 R26.1 U2.1(I)
AMP_OUT: R25.1 U2.2 U2.3(I)
AMP_SPDIF_RX: R28.1 U2.4
GPIO_IO22/SPDIF_RX: R28.2 ; off-sheet GPIO_IO22/SPDIF_RX
GPIO_IO23/SPDIF_TX: C35.2 ; off-sheet GPIO_IO23/SPDIF_TX
HASW_EN: E11.1 R222.1 U30.10(SEL) U31.5(EN)
HASW_IP2: R224.1 U31.8(IP)
HOSTB_USB_DN: J6.2(D-) L25.4
HOSTB_USB_DP: J6.3(D+) L25.3
HUB_OE: R221.2 U30.8(~{O}E)
JTAG_HDR_10: P4.10 R47.2
JTAG_POWER: C54.2 C221.1 D1.ANODE P4.2 R41.1 R42.2 U32.5(VCC)
JTAG_RST: P4.9 R46.2 U32.2(IN)
JTAG_RST_PU: D1.CATHODE R46.1
JTAG_TCK: P4.3 ; off-sheet JTAG_TCK
JTAG_TDI: P4.7 ; off-sheet JTAG_TDI
JTAG_TDO: P4.5 ; off-sheet JTAG_TDO
JTAG_TMS: P4.1 ; off-sheet JTAG_TMS
JTAGRST_OD: R48.1 R49.1 U32.4(OUT)
mux_PCIe_USB_DN: U30.7(HSD1-) ; off-sheet mux_PCIe_USB_DN
mux_PCIe_USB_DP: U30.1(HSD1+) ; off-sheet mux_PCIe_USB_DP
MUX_USB2_DN: L25.1 U30.6(HSD2-)
MUX_USB2_DP: L25.2 U30.2(HSD2+)
POR_B_3P3: R49.2 ; off-sheet POR_B_3P3
SPDIF_AUDIO_IN: C34.1 R29.2 ; off-sheet SPDIF_AUDIO_IN
SPDIF_AUDIO_OUT: C36.1 R27.2 R30.1 ; off-sheet SPDIF_AUDIO_OUT
SPDIF_OUT1C: C35.1 R27.1
SYS_RST_PMIC: R48.2 ; off-sheet SYS_RST_PMIC
USB2_DN: U30.5(D-) ; off-sheet USB2_DN
USB2_DP: U30.3(D+) ; off-sheet USB2_DP
USB2_ID: R217.1 ; off-sheet USB2_ID
USB2_VBUS_3V3: R220.2 ; off-sheet USB2_VBUS_3V3
VBUS_USB_B: C220.1 J6.1(VBUS) R220.1 U31.2(Vout) U31.3(Vout)

Not connected (* = marked no-connect by the designer): P4 8*; U31 1(FLG)*

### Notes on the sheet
- Host with mux for miniPCIe socket P18
- NOTE: USB1 multiplexing is controlled by jumper E11
- # 90-Ohm diff pairs
- (near R224) 1.05A LIMIT
- (near E11) E11 operation
  Open:       for USB conn. J6
  Close:      for miniPCIe socket P18
- (near C54) DNP
- TCK
- TMS
- (near P4) NXP refdes layout
- (near P4) GND
- (near P4) VCC
- TDI
- TDO
- (near R48) DNP
- SILKSCREEN:
  JTAG
- (near R49) DNP

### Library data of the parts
C34 C35 = 10nF, 25V, X7R, 10%, 0402: P/N: 151C10300S
C36 = 100pF, 50V, NPO, 5%, 0402: P/N: 151D10100S
C54 C221 C232 = 100nF, 10V, X7R, 10%, 0402_Dup1: P/N: 151B10400S
C218 = 100nF, 10V, X7R, 10%, 0402_Dup1: P/N: 151B10400S; Group: LAN2
C219 = 100nF, 10V, X7R, 10%, 0402: P/N: 151C10500S
C220 = 22uF,25V, 0805: P/N: 151C22620S
D1 = BAT54WS_0_Dup1: P/N: 130E05402S
E11 = HDR 1x2 100MIL TH JUMPER: P/N: 190C00200
J6 = USB Conn., Fem, Type A , TH, RA: P/N: 180K00400S
L25 = ESD_CHOKE_DIFFx2_10: P/N: 142D11801S
P4 = HDR 2x5 100MIL SMT: P/N: 190C01000S
R25 = 10K,1%,0402,1/16W: P/N: 161C10021S
R26 R27 R29 = 100R,1%,0402,1/16W: P/N: 161C10001S
R28 = 0R, 0402_0: P/N: 161C00005S
R30 = 220R,5%,0402,1/16W: P/N: 161C22005S
R41 R48 R49 = 0R, 0402_1: P/N: 161C00005S; CLABCONF0: DNP
R42 R47 = 0R, 0402_1: P/N: 161C00005S
R46 = 10K,1%,0402,1/16W_0_Dup1: P/N: 161C10021S; CLABCONF0: DNP
R217 = 0R, 0402: P/N: 161C00005S
R220 = 0R, 0402: P/N: 161C00005S; CLABCONF0: DNP
R221 = 10K,1%,0402,1/16W_0_Dup1: P/N: 161C10021S
R222 = 1M ,5%, 0402: P/N: 161C10021S
R224 = 100K, 1%, 0402, 1/16W: P/N: 161C20031S
U2 = 74LCX04 sgl gate TSSOP-14: P/N: 106D30040S
U30 = USB2_0.0 mux_Dup1: P/N: 116A72220S
U31 = RT9703,3A Power switch+FLG: P/N: 124S10080S
U32 = 74AUP1G07 , buffer ,LV: P/N: 106D20071S

## Sheet 06 CAN, RS485, GPIO, MI.SchDoc
size 420 x 297 mm; DocumentNumber: 6; SheetNumber: 6; SheetTotal: 12
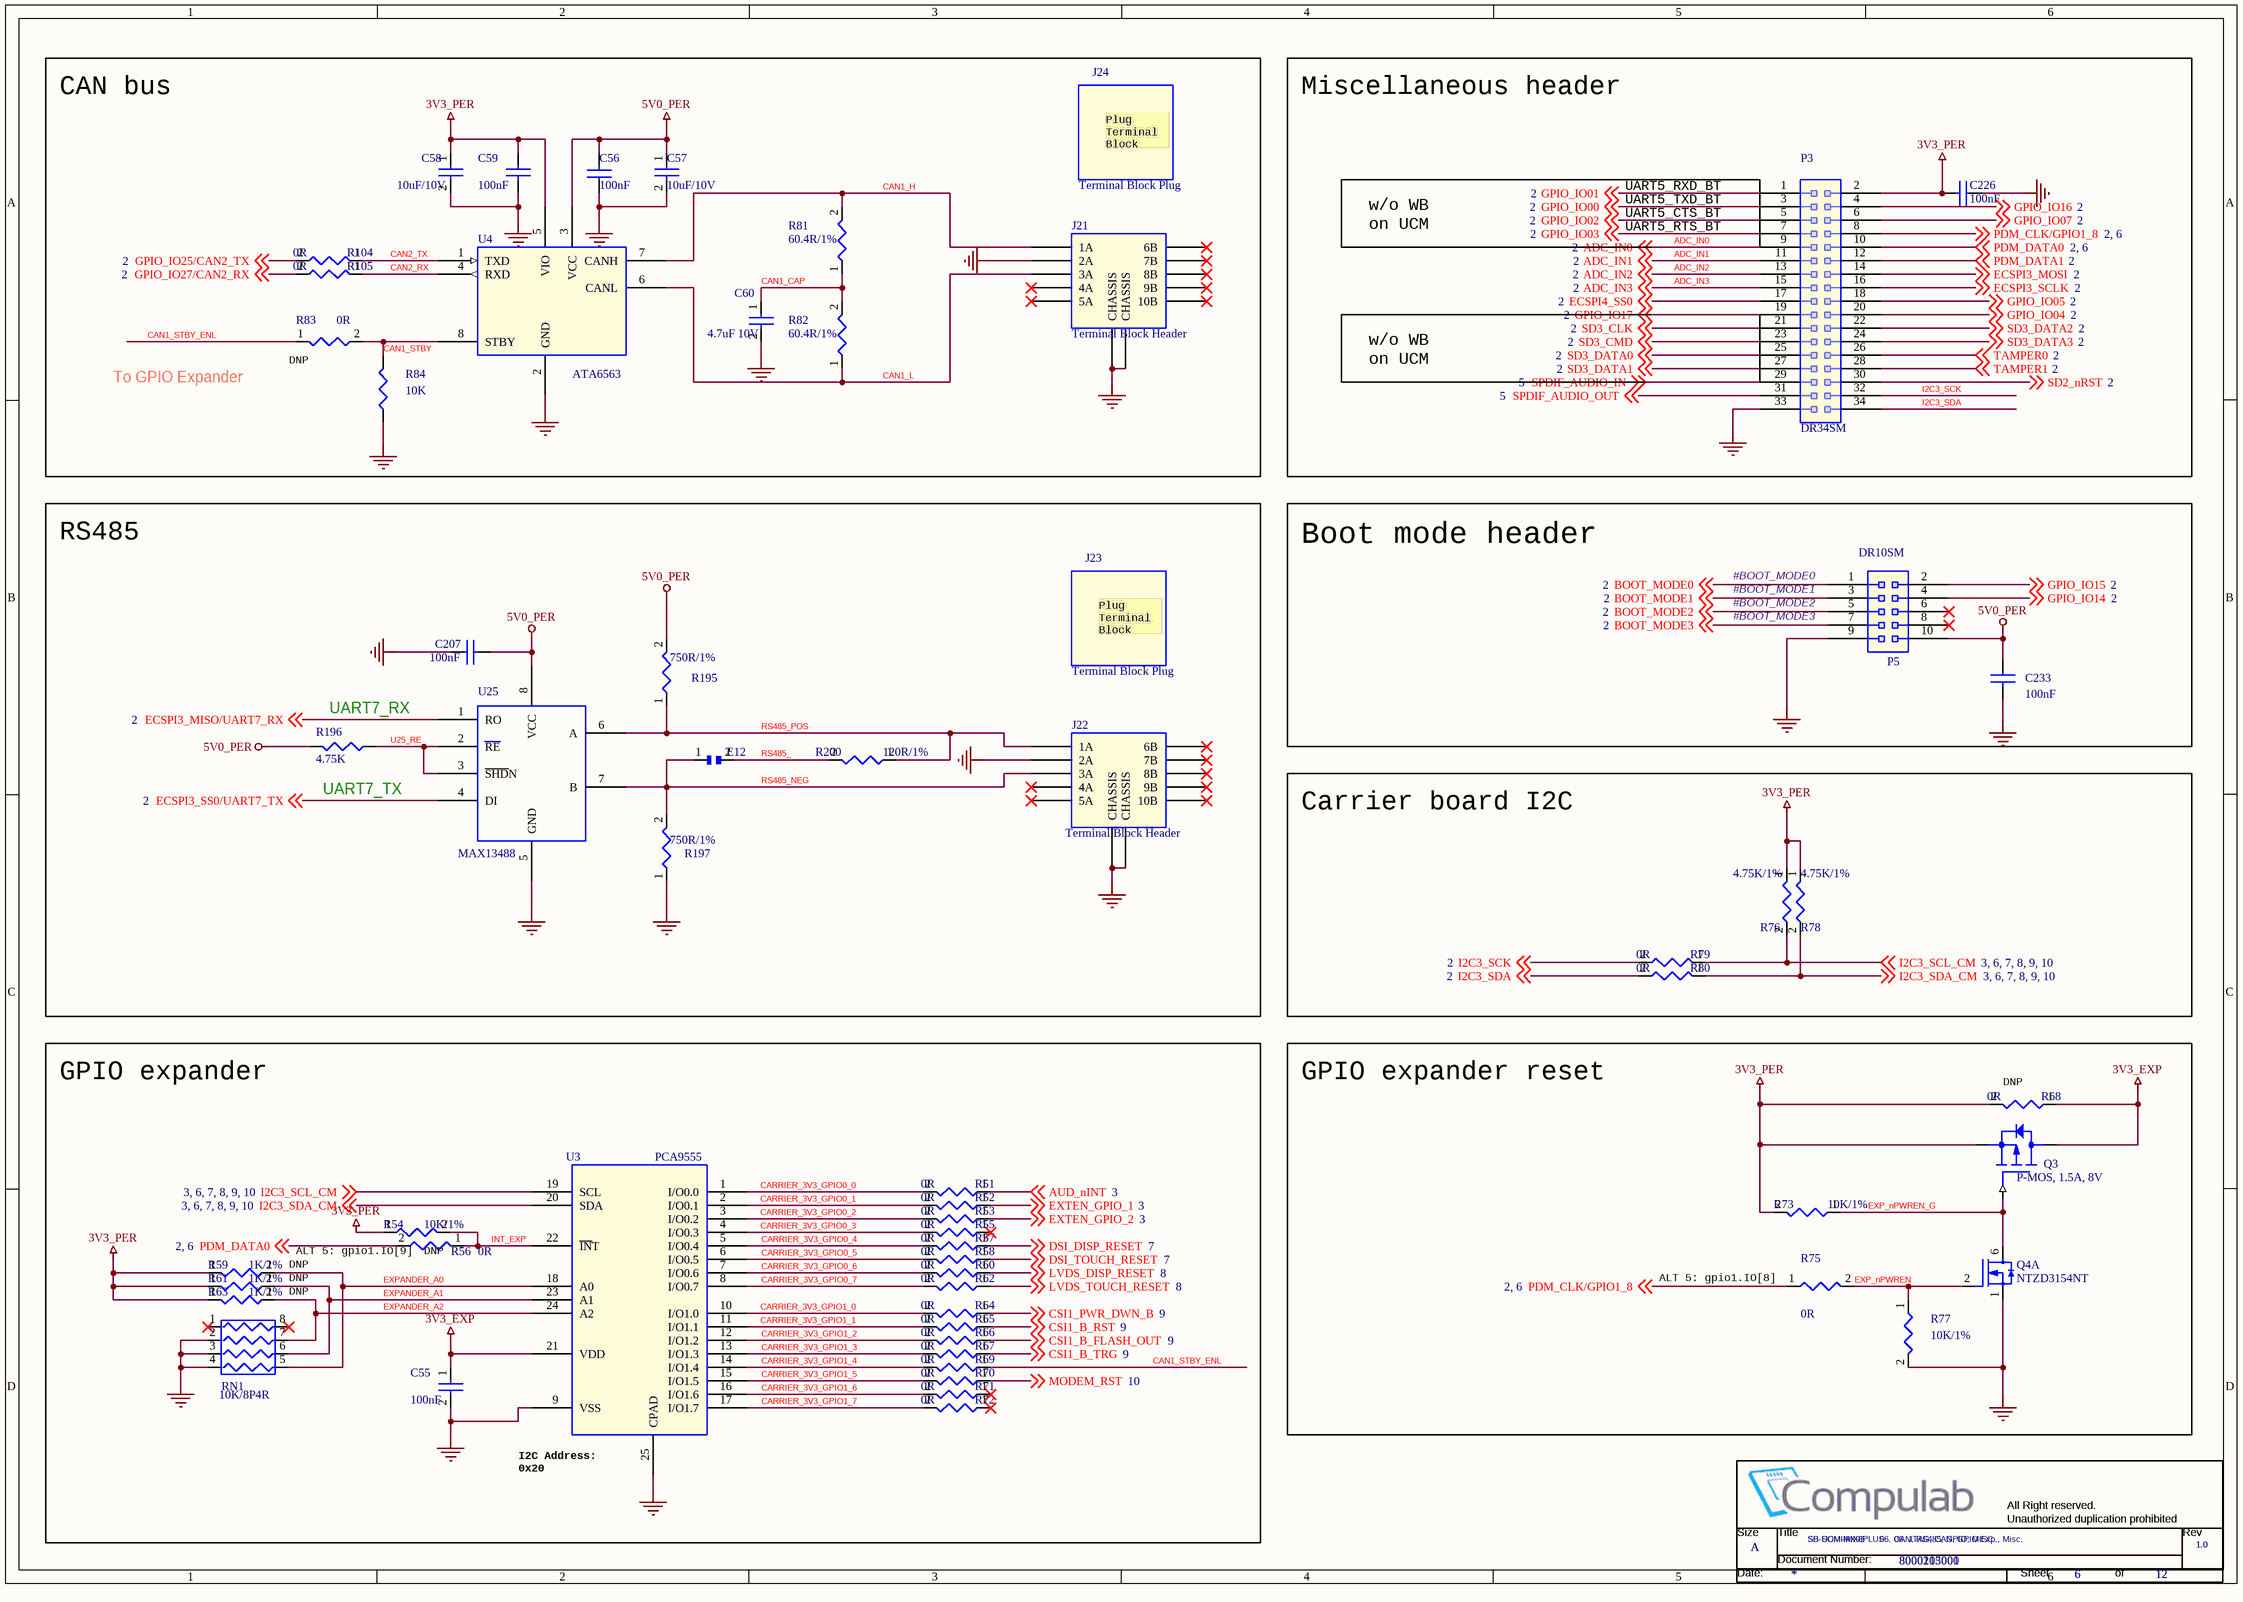
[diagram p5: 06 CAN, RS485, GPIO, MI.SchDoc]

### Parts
(Parts that share a designator on the sheet are numbered #1, #2 ... from top to bottom, then left to right.)
*#6  Title: SB-SOM-iMX8PLUS    06. JTAG, CAN, GPIO Exp., Misc.  Doc: 8000103001  RevCode: 1.0  Page Size: A  Page Number: 6  Page Count: 12  (hidden comment: CompuLabTitleBlk)  (graphical)
*#7  Title: SB-UCMIMX93      06. CAN, RS485, GPIO, MISC  Doc: 8000215000  RevCode: 1.0  Page Size: A  Page Number: 6  Page Count: 12  (hidden comment: CompuLabTitleBlk)  (graphical)
C55  100nF  [RC0402]
C56  100nF  [RC0402]
C57  10uF/10V  [RC0402]
C58  10uF/10V  [RC0402]
C59  100nF  [RC0402]
C60  4.7uF 10V  [RC0402]
C207  100nF  [RC0402]
C226  100nF  [RC0402]
C233  100nF  [RC0402]
E12  HDR1X2  [1X2THHDR]  (value not drawn)
J21  Terminal Block Header  [TB2.54mmRA-2x5P]
J22  Terminal Block Header  [TB2.54mmRA-2x5P]
J23  Terminal Block Plug  [1X2THHDR]  (mechanical)
J24  Terminal Block Plug  [1X2THHDR]  (mechanical)
P3  DR34SM  [2X17SMHDR]
P5  DR10SM  [2X5SMHDR]
Q3  P-MOS, 1.5A, 8V  [SOT23]
Q4  NTZD3154NT  [SOT-563-6]  (part A of 2)
R51  0R  [RC0402]
R52  0R  [RC0402]
R53  0R  [RC0402]
R54  10K/1%  [RC0402]
R55  0R  [RC0402]
R56  0R  [RC0402]
R57  0R  [RC0402]
R58  0R  [RC0402]
R59  1K/1%  [RC0402]
R60  0R  [RC0402]
R61  1K/1%  [RC0402]
R62  0R  [RC0402]
R63  1K/1%  [RC0402]
R64  0R  [RC0402]
R65  0R  [RC0402]
R66  0R  [RC0402]
R67  0R  [RC0402]
R68  0R  [RC0402]
R69  0R  [RC0402]
R70  0R  [RC0402]
R71  0R  [RC0402]
R72  0R  [RC0402]
R73  10K/1%  [RC0402]
R75  0R  [RC0402]
R76  4.75K/1%  [RC0402]
R77  10K/1%  [RC0402]
R78  4.75K/1%  [RC0402]
R79  0R  [RC0402]
R80  0R  [RC0402]
R81  60.4R/1%  [RC0402]
R82  60.4R/1%  [RC0402]
R83  0R  [RC0402]
R84  10K  [RC0402]
R104  0R  [RC0402]
R105  0R  [RC0402]
R195  750R/1%  [RC0402]
R196  4.75K  [RC0402]
R197  750R/1%  [RC0402]
R200  120R/1%  [RC0603]
RN1  10K/8P4R  [RESNET8P0805]
U3  PCA9555  [QFN4x4-24]
U4  ATA6563  [SOI8-150]
U25  MAX13488  [SO8-150]

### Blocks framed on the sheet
CAN bus: C56-C60 J21 J24 R81-R84 R104 R105 U4
Miscellaneous header: C226 P3
RS485: C207 E12 J22 J23 R195-R197 R200 U25
Boot mode header: C233 P5
Carrier board I2C: R76 R78-R80
GPIO expander: C55 R51-R67 R69-R72 RN1 U3
GPIO expander reset: Q3 Q4 R68 R73 R75 R77

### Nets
3V3_EXP: C55.1 Q3.3(D) R68.1 U3.21(VDD)
3V3_PER: C58.1 C59.1 C226.2 P3.2 Q3.2(S) R54.1 R59.1 R61.1 R63.1 R68.2 R73.2 R76.1 R78.1 U4.5(VIO)
5V0_PER: C56.2 C57.1 C207.2 C233.1 P5.10 R195.2 R196.2 U4.3(VCC) U25.8(VCC)
GND: C55.2 C56.1 C57.2 C58.2 C59.2 C60.2 C207.1 C226.1 C233.2 J21.2(2A) J21.CHASSIS J22.2(2A) J22.CHASSIS P3.33 P5.9 Q4.1(S) R77.2 R84.1 R197.1 RN1.2(RB1) RN1.3(RC1) RN1.4(RD1) U3.9(VSS) U3.25(CPAD) U4.2(GND) U25.5(GND)
ADC_IN0: P3.9 ; off-sheet ADC_IN0
ADC_IN1: P3.11 ; off-sheet ADC_IN1
ADC_IN2: P3.13 ; off-sheet ADC_IN2
ADC_IN3: P3.15 ; off-sheet ADC_IN3
AUD_nINT: R51.1 ; off-sheet AUD_nINT
BOOT_MODE0: P5.1 ; off-sheet BOOT_MODE0
BOOT_MODE1: P5.3 ; off-sheet BOOT_MODE1
BOOT_MODE2: P5.5 ; off-sheet BOOT_MODE2
BOOT_MODE3: P5.7 ; off-sheet BOOT_MODE3
CAN1_CAP: C60.1 R81.1 R82.2
CAN1_H: J21.1(1A) R81.2 U4.7(CANH)
CAN1_L: J21.3(3A) R82.1 U4.6(CANL)
CAN1_STBY: R83.2 R84.2 U4.8(STBY)
CAN1_STBY_ENL: R69.1 R83.1
CAN2_RX: R105.1 U4.4(RXD)
CAN2_TX: R104.1 U4.1(TXD)
CARRIER_3V3_GPIO0_0: R51.2 U3.1(I/O0.0)
CARRIER_3V3_GPIO0_1: R52.2 U3.2(I/O0.1)
CARRIER_3V3_GPIO0_2: R53.2 U3.3(I/O0.2)
CARRIER_3V3_GPIO0_3: R55.2 U3.4(I/O0.3)
CARRIER_3V3_GPIO0_4: R57.2 U3.5(I/O0.4)
CARRIER_3V3_GPIO0_5: R58.2 U3.6(I/O0.5)
CARRIER_3V3_GPIO0_6: R60.2 U3.7(I/O0.6)
CARRIER_3V3_GPIO0_7: R62.2 U3.8(I/O0.7)
CARRIER_3V3_GPIO1_0: R64.2 U3.10(I/O1.0)
CARRIER_3V3_GPIO1_1: R65.2 U3.11(I/O1.1)
CARRIER_3V3_GPIO1_2: R66.2 U3.12(I/O1.2)
CARRIER_3V3_GPIO1_3: R67.2 U3.13(I/O1.3)
CARRIER_3V3_GPIO1_4: R69.2 U3.14(I/O1.4)
CARRIER_3V3_GPIO1_5: R70.2 U3.15(I/O1.5)
CARRIER_3V3_GPIO1_6: R71.2 U3.16(I/O1.6)
CARRIER_3V3_GPIO1_7: R72.2 U3.17(I/O1.7)
CSI1_B_FLASH_OUT: R66.1 ; off-sheet CSI1_B_FLASH_OUT
CSI1_B_RST: R65.1 ; off-sheet CSI1_B_RST
CSI1_B_TRG: R67.1 ; off-sheet CSI1_B_TRG
CSI1_PWR_DWN_B: R64.1 ; off-sheet CSI1_PWR_DWN_B
DSI_DISP_RESET: R57.1 ; off-sheet DSI_DISP_RESET
DSI_TOUCH_RESET: R58.1 ; off-sheet DSI_TOUCH_RESET
ECSPI3_MISO/UART7_RX: U25.1(RO) ; off-sheet ECSPI3_MISO/UART7_RX
ECSPI3_MOSI: P3.14 ; off-sheet ECSPI3_MOSI
ECSPI3_SCLK: P3.16 ; off-sheet ECSPI3_SCLK
ECSPI3_SS0/UART7_TX: U25.4(DI) ; off-sheet ECSPI3_SS0/UART7_TX
ECSPI4_SS0: P3.17 ; off-sheet ECSPI4_SS0
EXP_nPWREN: Q4.2(G) R75.2 R77.1
EXP_nPWREN_G: Q3.1(G) Q4.6(D) R73.1
EXPANDER_A0: R59.2 RN1.5(RD2) U3.18(A0)
EXPANDER_A1: R61.2 RN1.6(RC2) U3.23(A1)
EXPANDER_A2: R63.2 RN1.7(RB2) U3.24(A2)
EXTEN_GPIO_1: R52.1 ; off-sheet EXTEN_GPIO_1
EXTEN_GPIO_2: R53.1 ; off-sheet EXTEN_GPIO_2
GPIO_IO00: P3.3 ; off-sheet GPIO_IO00
GPIO_IO01: P3.1 ; off-sheet GPIO_IO01
GPIO_IO02: P3.5 ; off-sheet GPIO_IO02
GPIO_IO03: P3.7 ; off-sheet GPIO_IO03
GPIO_IO04: P3.20 ; off-sheet GPIO_IO04
GPIO_IO05: P3.18 ; off-sheet GPIO_IO05
GPIO_IO07: P3.6 ; off-sheet GPIO_IO07
GPIO_IO14: P5.4 ; off-sheet GPIO_IO14
GPIO_IO15: P5.2 ; off-sheet GPIO_IO15
GPIO_IO16: P3.4 ; off-sheet GPIO_IO16
GPIO_IO17: P3.19 ; off-sheet GPIO_IO17
GPIO_IO25/CAN2_TX: R104.2 ; off-sheet GPIO_IO25/CAN2_TX
GPIO_IO27/CAN2_RX: R105.2 ; off-sheet GPIO_IO27/CAN2_RX
I2C3_SCK: P3.32 R79.2 ; off-sheet I2C3_SCK
I2C3_SCL_CM: R76.2 R79.1 U3.19(SCL) ; off-sheet I2C3_SCL_CM
I2C3_SDA: P3.34 R80.2 ; off-sheet I2C3_SDA
I2C3_SDA_CM: R78.2 R80.1 U3.20(SDA) ; off-sheet I2C3_SDA_CM
INT_EXP: R54.2 R56.1 U3.22(~{IN}T)
LVDS_DISP_RESET: R60.1 ; off-sheet LVDS_DISP_RESET
LVDS_TOUCH_RESET: R62.1 ; off-sheet LVDS_TOUCH_RESET
MODEM_RST: R70.1 ; off-sheet MODEM_RST
PDM_CLK/GPIO1_8: P3.8 R75.1 ; off-sheet PDM_CLK/GPIO1_8
PDM_DATA0: P3.10 R56.2 ; off-sheet PDM_DATA0
PDM_DATA1: P3.12 ; off-sheet PDM_DATA1
RS485_: E12.2 R200.2
RS485_NEG: E12.1 J22.3(3A) R197.2 U25.7(B)
RS485_POS: J22.1(1A) R195.1 R200.1 U25.6(A)
SD2_nRST: P3.30 ; off-sheet SD2_nRST
SD3_CLK: P3.21 ; off-sheet SD3_CLK
SD3_CMD: P3.23 ; off-sheet SD3_CMD
SD3_DATA0: P3.25 ; off-sheet SD3_DATA0
SD3_DATA1: P3.27 ; off-sheet SD3_DATA1
SD3_DATA2: P3.22 ; off-sheet SD3_DATA2
SD3_DATA3: P3.24 ; off-sheet SD3_DATA3
SPDIF_AUDIO_IN: P3.29 ; off-sheet SPDIF_AUDIO_IN
SPDIF_AUDIO_OUT: P3.31 ; off-sheet SPDIF_AUDIO_OUT
TAMPER0: P3.26 ; off-sheet TAMPER0
TAMPER1: P3.28 ; off-sheet TAMPER1
U25_RE: R196.1 U25.2(RE) U25.3(~{SHD}N)

Not connected (* = marked no-connect by the designer): J21 4(4A)* 5(5A)* 6(6B)* 7(7B)* 8(8B)* 9(9B)* 10(10B)*; J22 4(4A)* 5(5A)* 6(6B)* 7(7B)* 8(8B)* 9(9B)* 10(10B)*; P5 6* 8*; R55 1*; R71 1*; R72 1*; RN1 1(RA1)* 8(RA2)*

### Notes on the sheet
- UART5_RXD_BT
- w/o WB
  on UCM
- UART5_TXD_BT
- UART5_CTS_BT
- UART5_RTS_BT
- To GPIO Expander
- (near R83) DNP
- #BOOT_MODE0
- #BOOT_MODE1
- #BOOT_MODE3
- #BOOT_MODE2
- (near R196) UART7_RX
- (near R196) UART7_TX
- (near R68) DNP
- DNP
- ALT 5: gpio1.IO[9]
- (near R56) DNP
- ALT 5: gpio1.IO[8]
- (near U3) I2C Address:
  0x20

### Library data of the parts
C55 = 100nF, 10V, X7R, 10%, 0402_Dup1: P/N: 151B10400S
C56 C59 C207 C226 C233 = 100nF, 10V, X7R, 10%, 0402_0: P/N: 151B10400S
C57 C58 = 10uF 10V 20% 0402: as C45 on sheet 02 SOM Connectors
C60 = 4.7uF 0402 10V 20%: P/N: 151B47500S
E12 = HDR 1x2 100MIL TH JUMPER: P/N: 190C00200
J21 J22 = Terminal Block Header 2x5P 2.54: P/N: 178B01000
J23 J24 = Terminal Block Plug: P/N: 178A01000
P3 = HDR 2x17 100MIL SMT: P/N: 190C03400S
P5 = HDR 2x5 100MIL SMT: P/N: 190C01000S
Q3 = P-MOS, 1.5A, 8V: P/N: 131D21010S
Q4 = N-MOSFET_Dual: P/N: 131D31540S
R51-R53 R55 R57 R58 R60 R62 R64-R67 R69-R72 R75 = 0R, 0402_1: P/N: 161C00005S
R54 = 10K,1%,0402,1/16W_0_Dup1: P/N: 161C10021S
R56 = 0R, 0402_0: P/N: 161C00005S; CLABCONF0: DNP
R59 R61 R63 = 1K,1%,0402,1/16W: P/N: 161C10011S; CLABCONF0: DNP; Group: CAN
R68 R83 = 0R, 0402_1: P/N: 161C00005S; CLABCONF0: DNP
R73 R77 = 10K,1%,0402,1/16W: P/N: 161C10021S
R76 R78 = 4_0.75K,1%,0402,1/16W: P/N: 161C47511S
R79 R80 R104 R105 = 0R, 0402_0: P/N: 161C00005S
R81 R82 = 60.4R/1%, 0402: P/N: 161C60R41S
R84 = 10K,1%,0402,1/16W_0: P/N: 161C10021S
R195 R197 = 10K,1%,0402,1/16W: P/N: 161C75001S
R196 = 10K,1%,0402,1/16W_0: P/N: 161C47511S; Group: Always
R200 = 120R/1%, 0603: P/N: 161D12001S
RN1 = RN,10K,8P4R@0805: P/N: 163K04103S
U3 = PCA9555_1: P/N: 116B95550S
U4 = ATA6563: P/N: 116A00380S
U25 = SN65HVD72D_0: P/N: 116A00430S

## Sheet 07 MIPI-DSI LCD.SchDoc
size 420 x 297 mm; DocumentNumber: 7; SheetNumber: 7; SheetTotal: 12
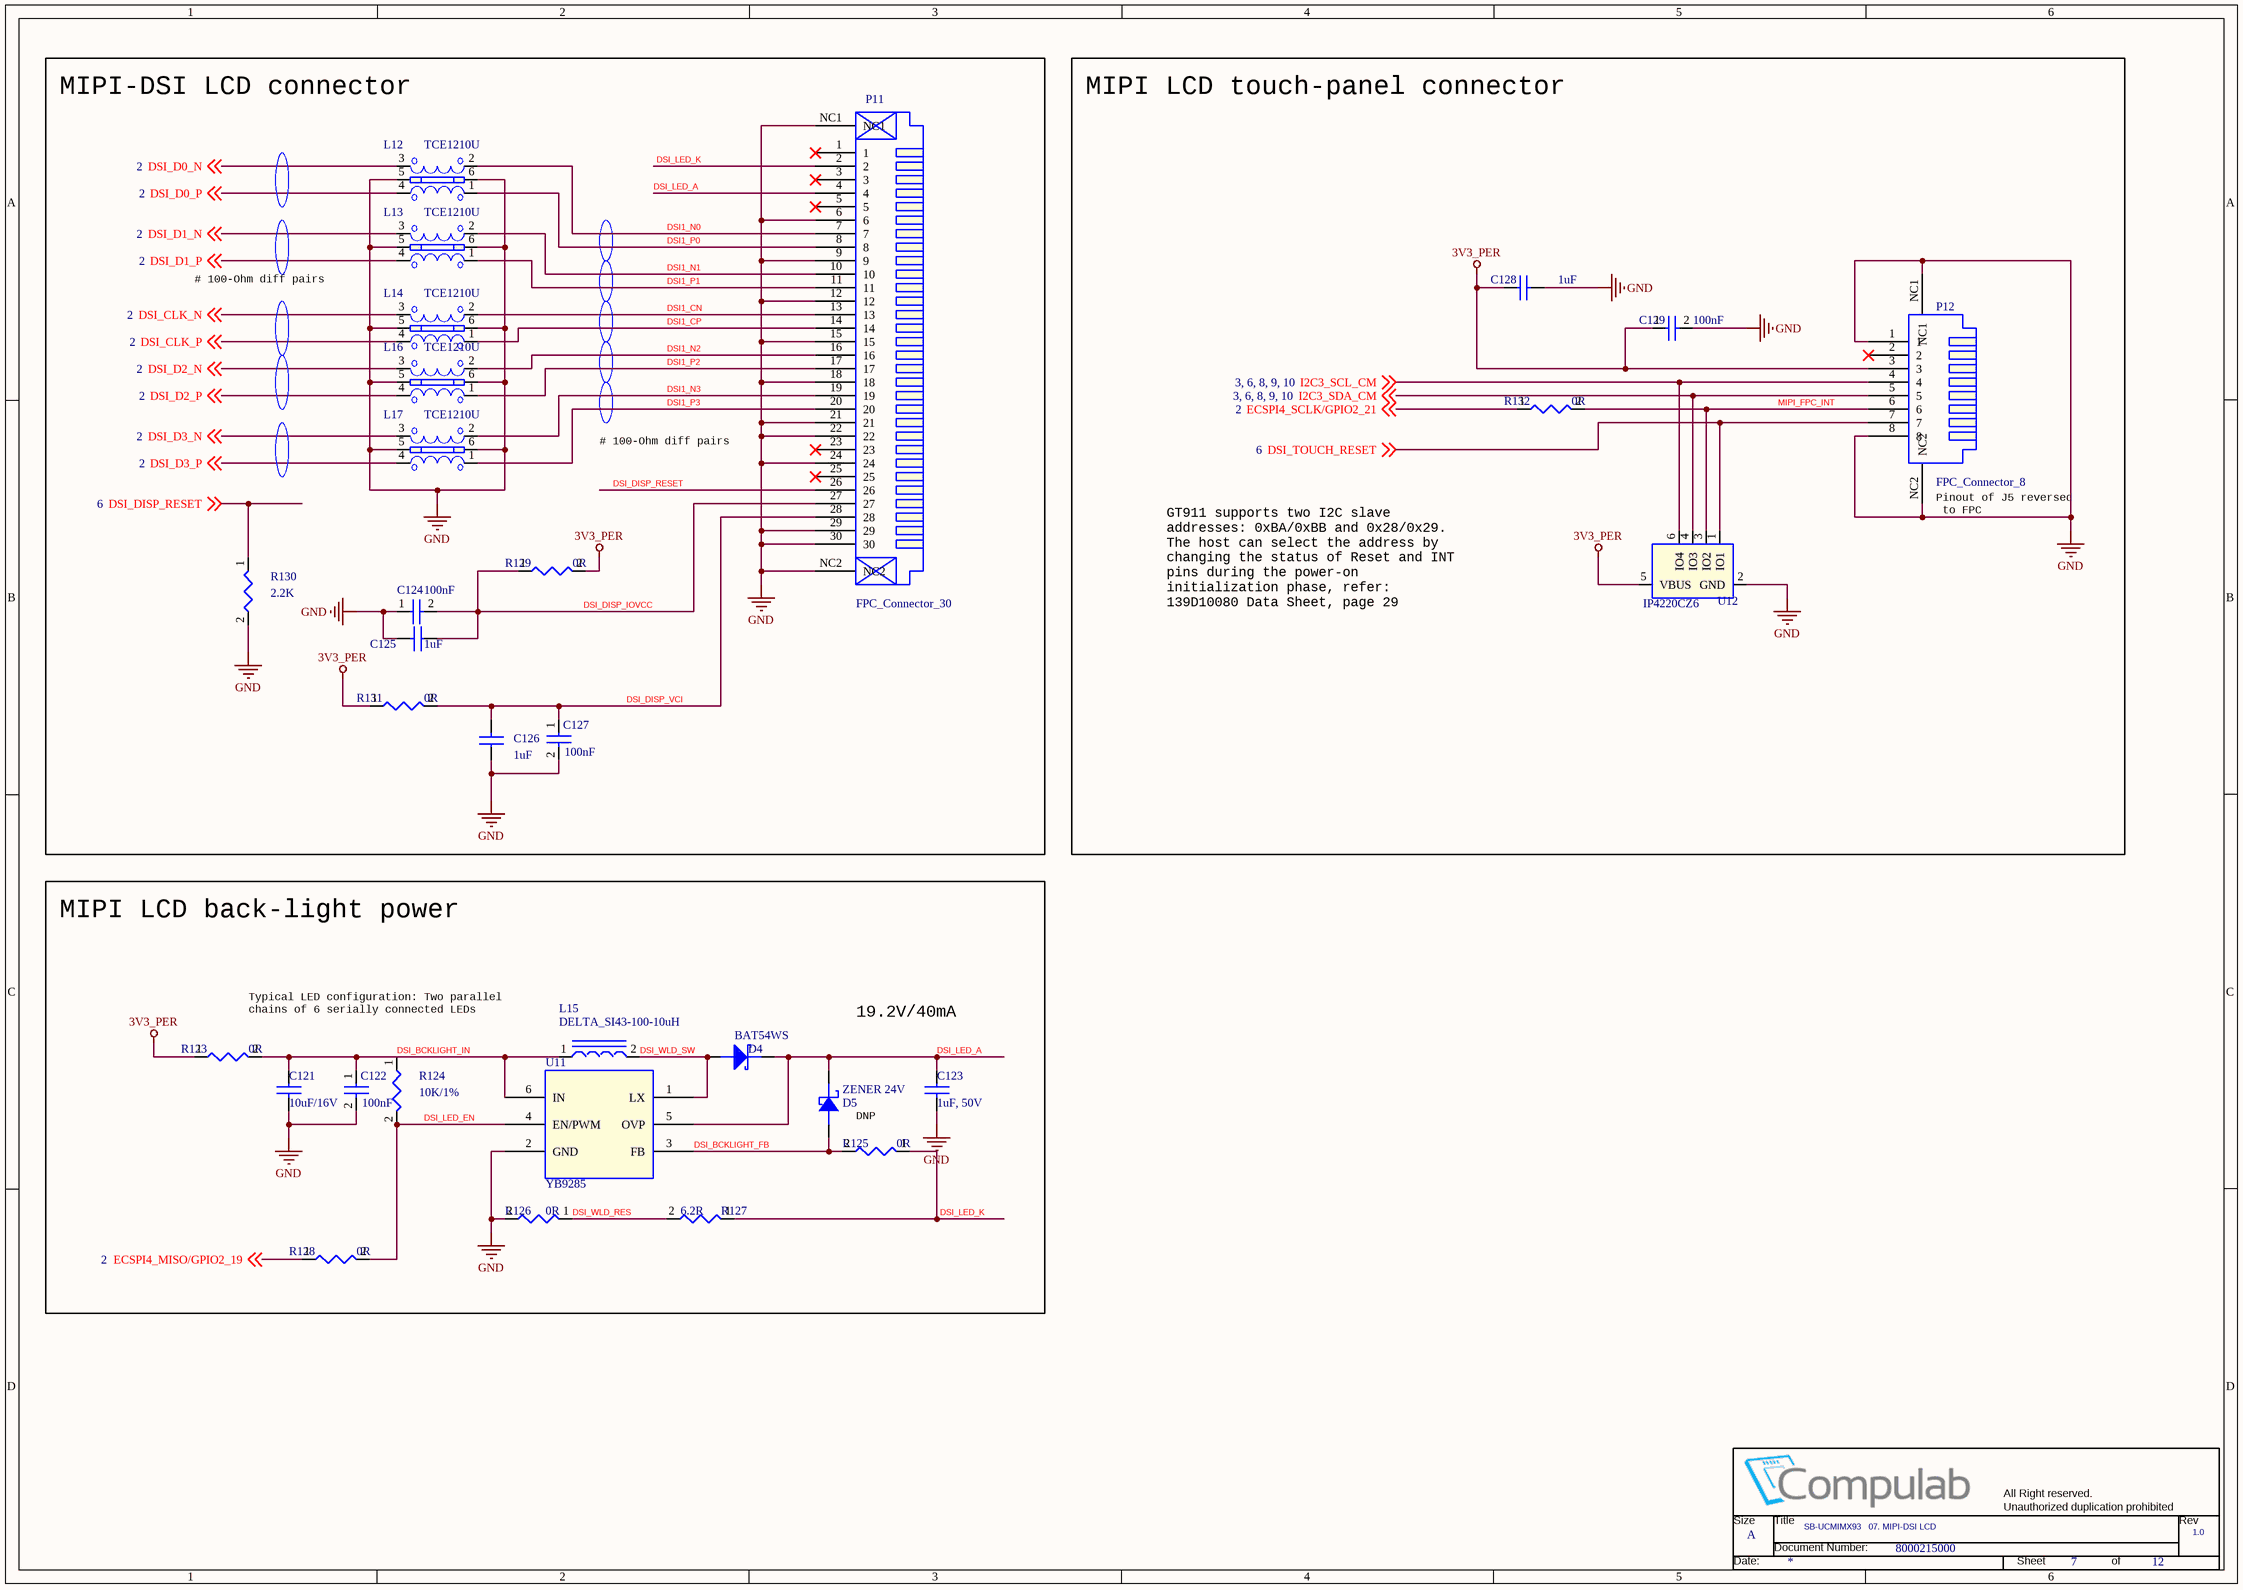
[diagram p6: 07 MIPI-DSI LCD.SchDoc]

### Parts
(Parts that share a designator on the sheet are numbered #1, #2 ... from top to bottom, then left to right.)
*#8  Title: SB-UCMIMX93   07. MIPI-DSI LCD  Doc: 8000215000  RevCode: 1.0  Page Size: A  Page Number: 7  Page Count: 12  (hidden comment: CompuLabTitleBlk)  (graphical)
C121  10uF/16V  [RC0603]
C122  100nF  [RC0402]
C123  1uF, 50V  [RC0603]
C124  100nF  [RC0402]
C125  1uF  [RC0402]
C126  1uF  [RC0402]
C127  100nF  [RC0402]
C128  1uF  [RC0402]
C129  100nF  [RC0402]
D4  BAT54WS  [SOD-323]
D5  ZENER 24V  [SOD-123]
L12  TCE1210U  [EMI1012-ESD]
L13  TCE1210U  [EMI1012-ESD]
L14  TCE1210U  [EMI1012-ESD]
L15  DELTA_SI43-100-10uH  [IND4x4x2_5]
L16  TCE1210U  [EMI1012-ESD]
L17  TCE1210U  [EMI1012-ESD]
P11  FPC_Connector_30  [FPC_30]
P12  FPC_Connector_8  [FPC_8]
R123  0R  [RC0402]
R124  10K/1%  [RC0402]
R125  0R  [RC0402]
R126  0R  [RC0402]
R127  6.2R  [RC0402]
R128  0R  [RC0402]
R129  0R  [RC0402]
R130  2.2K  [RC0402]
R131  0R  [RC0402]
R132  0R  [RC0402]
U11  YB9285  [SOT23-6L]
U12  IP4220CZ6  [SOT23-6L]

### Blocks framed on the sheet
MIPI-DSI LCD connector: C124-C127 L12-L14 L16 L17 P11 R129-R131
MIPI LCD touch-panel connector: C128 C129 P12 R132 U12
MIPI LCD back-light power: C121-C123 D4 D5 L15 R123-R128 U11

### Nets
3V3_PER: C128.1 C129.1 P12.3 R123.1 R129.2 R131.1 U12.5(VBUS)
GND: C121.2 C122.2 C123.2 C124.1 C125.2 C126.1 C127.2 C128.2 C129.2 L12.5(GND) L12.6(GND) L13.5(GND) L13.6(GND) L14.5(GND) L14.6(GND) L16.5(GND) L16.6(GND) L17.5(GND) L17.6(GND) P11.6 P11.9 P11.12 P11.15 P11.18 P11.21 P11.22 P11.24 P11.29 P11.30 P11.NC1 P11.NC2 P12.1 P12.8 P12.NC1 P12.NC2 R126.2 R130.2 U11.2(GND) U12.2(GND)
DSI1_CN: L14.2 P11.13
DSI1_CP: L14.1 P11.14
DSI1_N0: L12.2 P11.7
DSI1_N1: L13.2 P11.10
DSI1_N2: L16.2 P11.16
DSI1_N3: L17.2 P11.19
DSI1_P0: L12.1 P11.8
DSI1_P1: L13.1 P11.11
DSI1_P2: L16.1 P11.17
DSI1_P3: L17.1 P11.20
DSI_BCKLIGHT_FB: D5.2(ANODE) R125.2 U11.3(FB)
DSI_BCKLIGHT_IN: C121.1 C122.1 L15.1 R123.2 R124.1 U11.6(IN)
DSI_CLK_N: L14.3 ; off-sheet DSI_CLK_N
DSI_CLK_P: L14.4 ; off-sheet DSI_CLK_P
DSI_D0_N: L12.3 ; off-sheet DSI_D0_N
DSI_D0_P: L12.4 ; off-sheet DSI_D0_P
DSI_D1_N: L13.3 ; off-sheet DSI_D1_N
DSI_D1_P: L13.4 ; off-sheet DSI_D1_P
DSI_D2_N: L16.3 ; off-sheet DSI_D2_N
DSI_D2_P: L16.4 ; off-sheet DSI_D2_P
DSI_D3_N: L17.3 ; off-sheet DSI_D3_N
DSI_D3_P: L17.4 ; off-sheet DSI_D3_P
DSI_DISP_IOVCC: C124.2 C125.1 P11.27 R129.1
DSI_DISP_RESET: P11.26 R130.1 ; off-sheet DSI_DISP_RESET
DSI_DISP_VCI: C126.2 C127.1 P11.28 R131.2
DSI_LED_A: C123.1 D4.CATHODE D5.1(CATHODE) P11.4 U11.5(OVP)
DSI_LED_EN: R124.2 R128.2 U11.4(EN/PWM)
DSI_LED_K: P11.2 R125.1 R127.1
DSI_TOUCH_RESET: P12.7 U12.1(IO1) ; off-sheet DSI_TOUCH_RESET
DSI_WLD_RES: R126.1 R127.2
DSI_WLD_SW: D4.ANODE L15.2 U11.1(LX)
ECSPI4_MISO/GPIO2_19: R128.1 ; off-sheet ECSPI4_MISO/GPIO2_19
ECSPI4_SCLK/GPIO2_21: R132.1 ; off-sheet ECSPI4_SCLK/GPIO2_21
I2C3_SCL_CM: P12.4 U12.6(IO4) ; off-sheet I2C3_SCL_CM
I2C3_SDA_CM: P12.5 U12.4(IO3) ; off-sheet I2C3_SDA_CM
MIPI_FPC_INT: P12.6 R132.2 U12.3(IO2)

Not connected (* = marked no-connect by the designer): P11 1* 3* 5* 23* 25*; P12 2*

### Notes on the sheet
- # 100-Ohm diff pairs
- (near P12) Pinout of J5 reversed
  to FPC
- GT911 supports two I2C slave
  addresses: 0xBA/0xBB and 0x28/0x29.
  The host can select the address by
  changing the status of Reset and INT
  pins during the power-on
  initialization phase, refer:
  139D10080 Data Sheet, page 29
- Typical LED configuration: Two parallel
  chains of 6 serially connected LEDs
- 19.2V/40mA
- DNP

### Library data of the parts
C121 = 10uF,6.3V,0603,20%X5R_Dup1: P/N: 151C10610S
C122 C124 C127 C129 = 100nF, 10V, X7R, 10%, 0402_Dup1: P/N: 151B10400S
C123 = 1uF,X5R,6.3V,0402: P/N: 151D10510S
C125 C126 C128 = 1uF,X5R,6.3V,0402: P/N: 151B10500S
D4 = BAT54WS_0_Dup1: P/N: 130E05402S
D5 = ZENER 24V 500mW SOD-123: P/N: 130B24000S; CLABCONF0: DNP
L12-L14 L16 L17 = ESD_CHOKE_DIFFx2_10: P/N: 142D11801S
L15 = INC DELTA SI43-100, 10uH: P/N: 147A10001S; CLABCONF1: <null>
P11 = FPC_Connector_0: P/N: 182P03002S
P12 = FPC_Connector_4: P/N: 182P00802S
R123 R125 R129 R131 R132 = 0R, 0402: P/N: 161C00005S
R124 = 10K,1%,0402,1/16W_0_Dup1: P/N: 161C10021S
R126 = 2.2R,5%,0402,1/16W: P/N: 161C00005S
R127 = 2.2R,5%,0402,1/16W: P/N: 161C06R25S
R128 = 0R, 0402: P/N: 161C00005S; CLABCONF0: DNP
R130 = 2.2K,5%,0402.1/16W: P/N: 161C22015S
U11 = AIC1647_0: P/N: 123C40000S
U12 = IP4220CZ6_0: P/N: 132D42200S

## Sheet 08 LVDS LCD.SchDoc
size 420 x 297 mm; DocumentNumber: 8; SheetNumber: 8; SheetTotal: 12
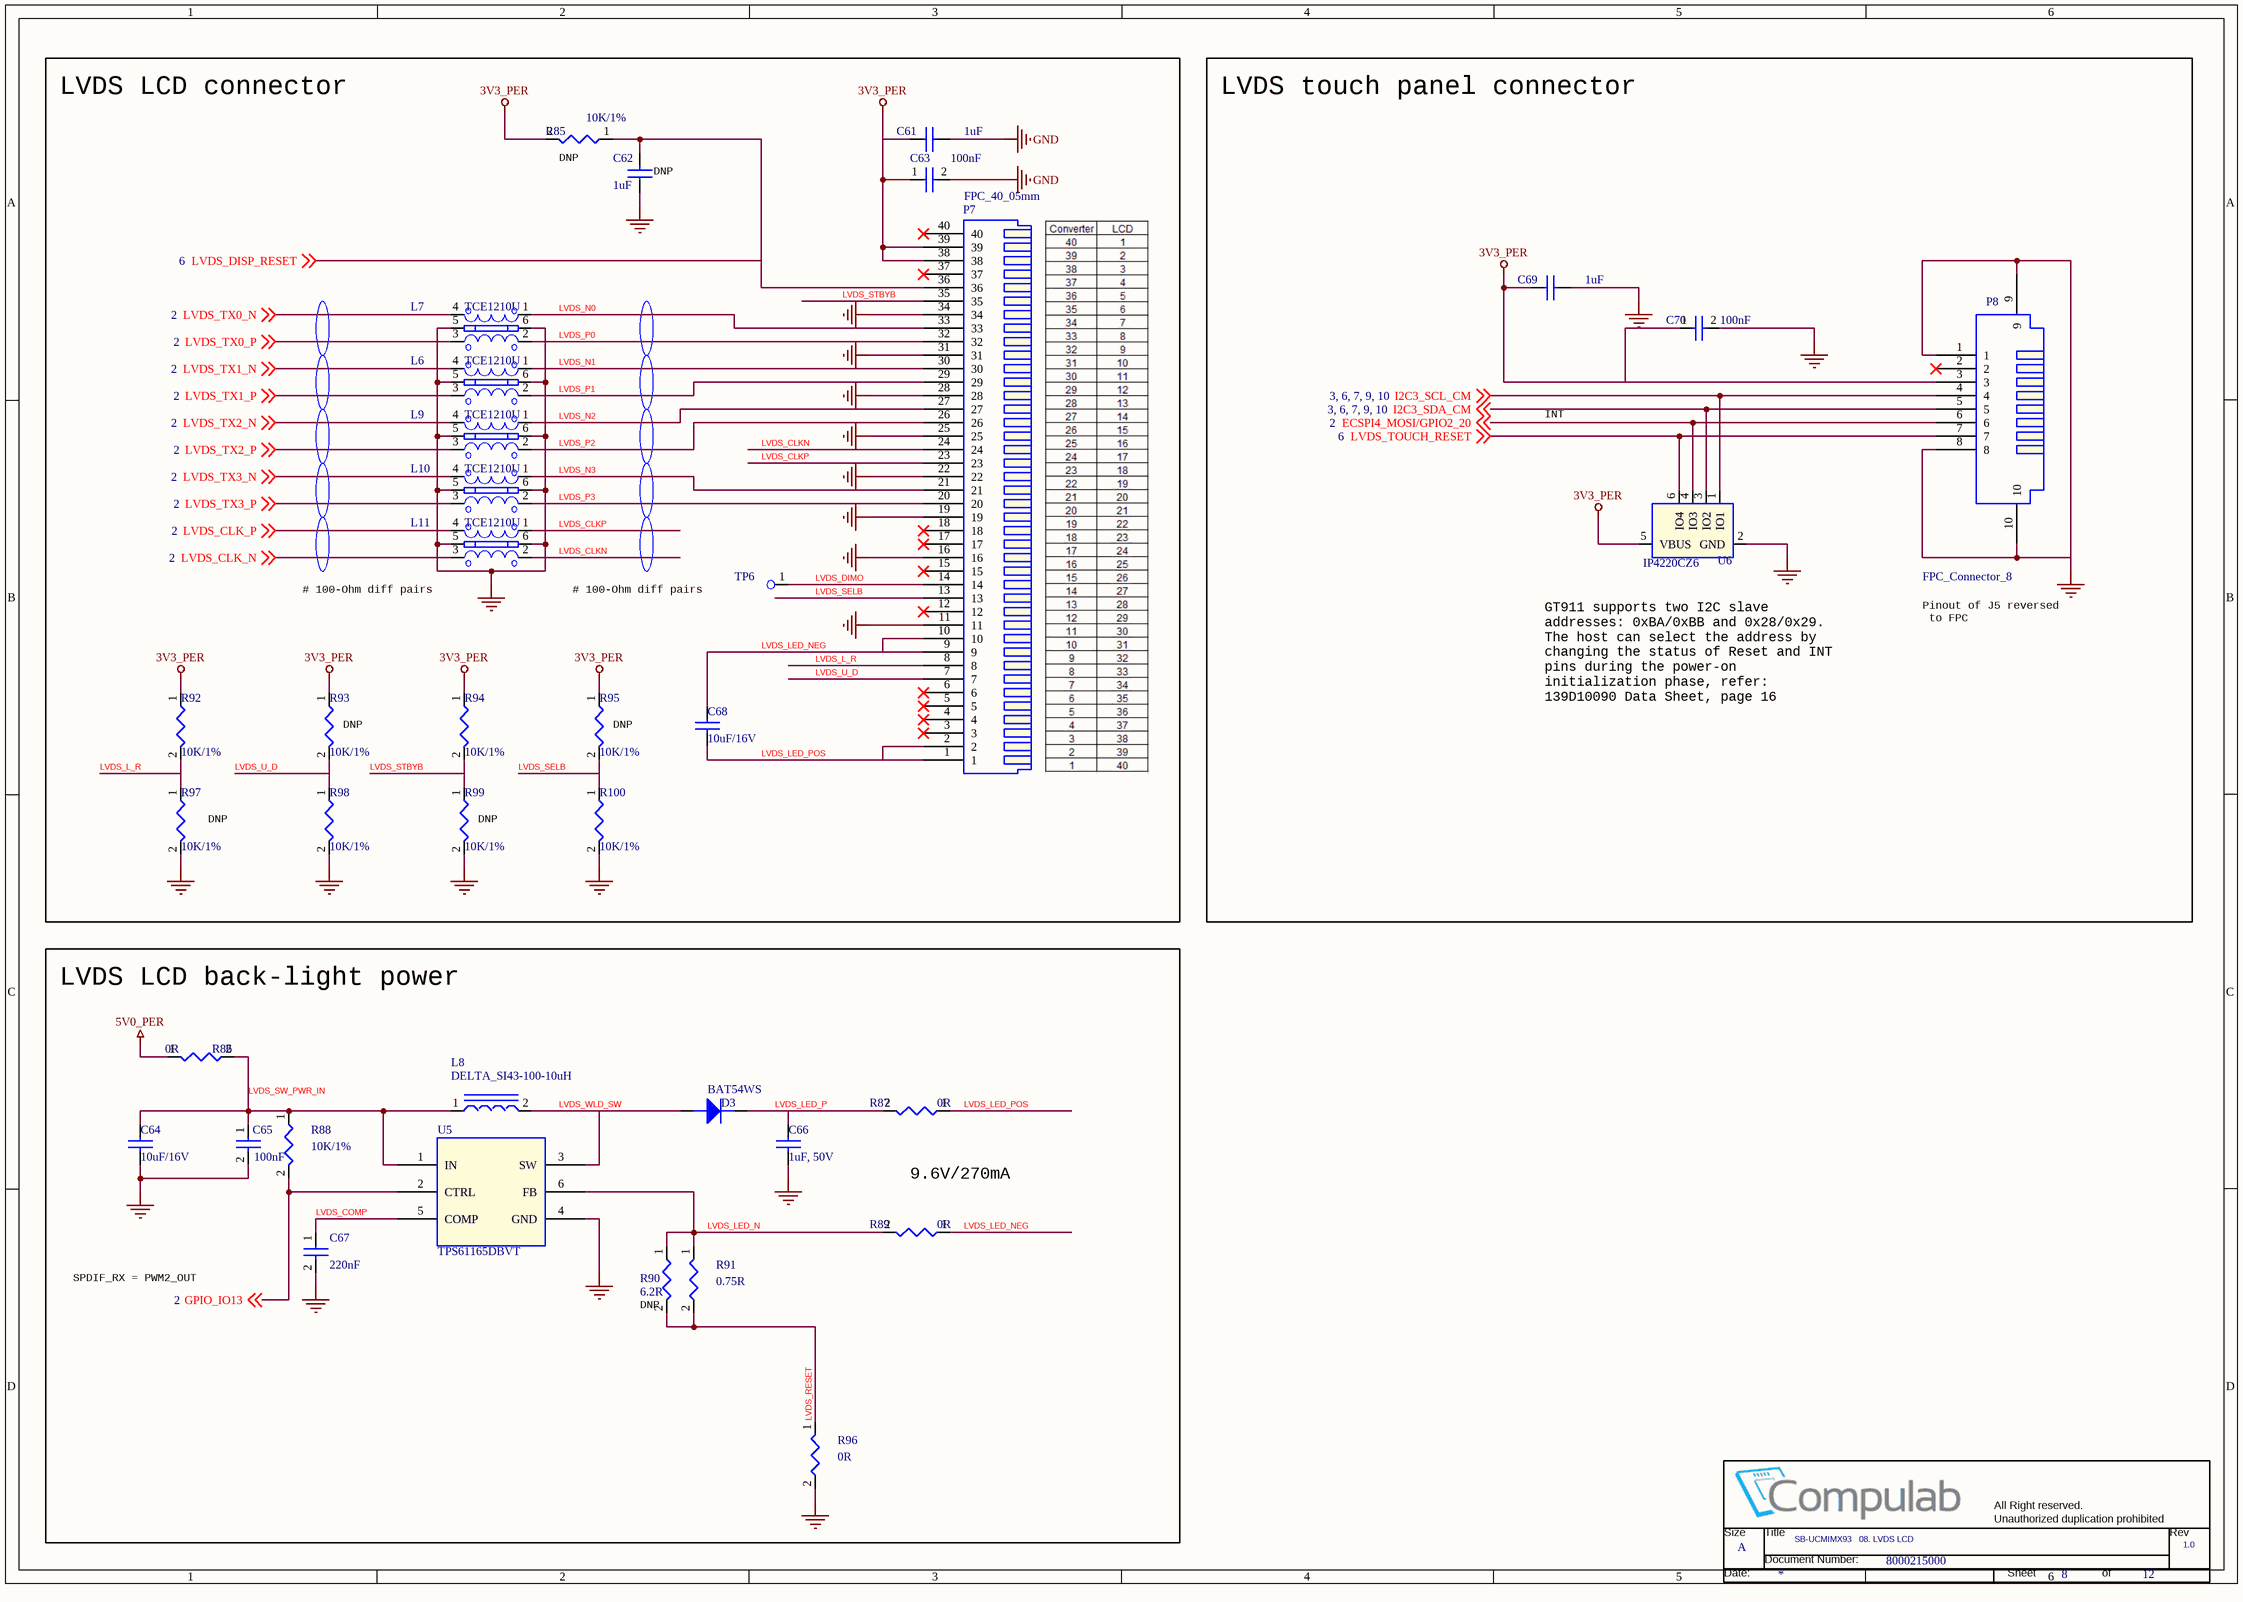
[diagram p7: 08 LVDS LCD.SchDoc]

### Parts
(Parts that share a designator on the sheet are numbered #1, #2 ... from top to bottom, then left to right.)
*#9  Title: SB-UCMIMX93   08. LVDS LCD  Doc: 8000215000  RevCode: 1.0  Page Size: A  Page Number: 8  Page Count: 12  (hidden comment: CompuLabTitleBlk)  (graphical)
C61  1uF  [RC0402]
C62  1uF  [RC0402]
C63  100nF  [RC0402]
C64  10uF/16V  [RC0603]
C65  100nF  [RC0402]
C66  1uF, 50V  [RC0603]
C67  220nF  [RC0402]
C68  10uF/16V  [RC0603]
C69  1uF  [RC0402]
C70  100nF  [RC0402]
D3  BAT54WS  [SOD-323]
L6  TCE1210U  [EMI1012-ESD]
L7  TCE1210U  [EMI1012-ESD]
L8  DELTA_SI43-100-10uH  [IND4x4x2_5]
L9  TCE1210U  [EMI1012-ESD]
L10  TCE1210U  [EMI1012-ESD]
L11  TCE1210U  [EMI1012-ESD]
P7  FPC_40_05mm  [FPC05SM40-1]
P8  FPC_Connector_8  [FPC_8]
R85  10K/1%  [RC0402]
R86  0R  [RC1206]
R87  0R  [RC1206]
R88  10K/1%  [RC0402]
R89  0R  [RC1206]
R90  6.2R  [RC0402]
R91  0.75R  [RC0402]
R92  10K/1%  [RC0402]
R93  10K/1%  [RC0402]
R94  10K/1%  [RC0402]
R95  10K/1%  [RC0402]
R96  0R  [RC0402]
R97  10K/1%  [RC0402]
R98  10K/1%  [RC0402]
R99  10K/1%  [RC0402]
R100  10K/1%  [RC0402]
TP6  TESTPOINT  [TESTPOINT]  (value not drawn)
U5  TPS61165DBVT  [SOT23-6]
U6  IP4220CZ6  [SOT23-6L]

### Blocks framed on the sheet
LVDS LCD connector: C61-C63 C68 L6 L7 L9-L11 P7 R85 R92-R95 R97-R100 TP6
LVDS touch panel connector: C69 C70 P8 U6
LVDS LCD back-light power: C64-C67 D3 L8 R86-R91 R96 U5

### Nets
3V3_PER: C61.1 C63.1 C69.1 C70.1 P7.38 P7.39 P8.3 R85.2 R92.1 R93.1 R94.1 R95.1 U6.5(VBUS)
5V0_PER: R86.1
GND: C61.2 C62.1 C63.2 C64.2 C65.2 C66.2 C67.2 C69.2 C70.2 L6.5(GND) L6.6(GND) L7.5(GND) L7.6(GND) L9.5(GND) L9.6(GND) L10.5(GND) L10.6(GND) L11.5(GND) L11.6(GND) P7.11 P7.16 P7.19 P7.22 P7.25 P7.28 P7.31 P7.34 P8.1 P8.8 P8.9 P8.10 R96.2 R97.2 R98.2 R99.2 R100.2 U5.4(GND) U6.2(GND)
ECSPI4_MOSI/GPIO2_20: P8.6 U6.4(IO3) ; off-sheet ECSPI4_MOSI/GPIO2_20
GPIO_IO13: R88.2 U5.2(CTRL) ; off-sheet GPIO_IO13
I2C3_SCL_CM: P8.4 U6.1(IO1) ; off-sheet I2C3_SCL_CM
I2C3_SDA_CM: P8.5 U6.3(IO2) ; off-sheet I2C3_SDA_CM
LVDS_CLK_N: L11.3 ; off-sheet LVDS_CLK_N
LVDS_CLK_P: L11.4 ; off-sheet LVDS_CLK_P
LVDS_CLKN: L11.2 P7.24
LVDS_CLKP: L11.1 P7.23
LVDS_COMP: C67.1 U5.5(COMP)
LVDS_DIMO: P7.14 TP6.1
LVDS_DISP_RESET: C62.2 P7.36 R85.1 ; off-sheet LVDS_DISP_RESET
LVDS_L_R: P7.8 R92.2 R97.1
LVDS_LED_N: R89.2 R90.1 R91.1 U5.6(FB)
LVDS_LED_NEG: C68.1 P7.9 P7.10 R89.1
LVDS_LED_P: C66.1 D3.CATHODE R87.2
LVDS_LED_POS: C68.2 P7.1 P7.2 R87.1
LVDS_N0: L7.1 P7.33
LVDS_N1: L6.1 P7.30
LVDS_N2: L9.1 P7.27
LVDS_N3: L10.1 P7.21
LVDS_P0: L7.2 P7.32
LVDS_P1: L6.2 P7.29
LVDS_P2: L9.2 P7.26
LVDS_P3: L10.2 P7.20
LVDS_RESET: R90.2 R91.2 R96.1
LVDS_SELB: P7.13 R95.2 R100.1
LVDS_STBYB: P7.35 R94.2 R99.1
LVDS_SW_PWR_IN: C64.1 C65.1 L8.1 R86.2 R88.1 U5.1(IN)
LVDS_TOUCH_RESET: P8.7 U6.6(IO4) ; off-sheet LVDS_TOUCH_RESET
LVDS_TX0_N: L7.4 ; off-sheet LVDS_TX0_N
LVDS_TX0_P: L7.3 ; off-sheet LVDS_TX0_P
LVDS_TX1_N: L6.4 ; off-sheet LVDS_TX1_N
LVDS_TX1_P: L6.3 ; off-sheet LVDS_TX1_P
LVDS_TX2_N: L9.4 ; off-sheet LVDS_TX2_N
LVDS_TX2_P: L9.3 ; off-sheet LVDS_TX2_P
LVDS_TX3_N: L10.4 ; off-sheet LVDS_TX3_N
LVDS_TX3_P: L10.3 ; off-sheet LVDS_TX3_P
LVDS_U_D: P7.7 R93.2 R98.1
LVDS_WLD_SW: D3.ANODE L8.2 U5.3(SW)

Not connected (* = marked no-connect by the designer): P7 3* 4* 5* 6* 12* 15* 17* 18* 37* 40*; P8 2*

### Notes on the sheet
- (near R85) DNP
- (near C62) DNP
- INT
- # 100-Ohm diff pairs
- Pinout of J5 reversed
  to FPC
- (near R93) DNP
- (near R95) DNP
- GT911 supports two I2C slave
  addresses: 0xBA/0xBB and 0x28/0x29.
  The host can select the address by
  changing the status of Reset and INT
  pins during the power-on
  initialization phase, refer:
  139D10090 Data Sheet, page 16
- (near R97) DNP
- (near R99) DNP
- 9.6V/270mA
- SPDIF_RX = PWM2_OUT
- (near R90) DNP

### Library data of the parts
C61 C69 = 1uF,X5R,6.3V,0402: P/N: 151B10500S
C62 = 1uF,X5R,6.3V,0402: P/N: 151B10500S; CLABCONF0: DNP
C63 C65 C70 = 100nF, 10V, X7R, 10%, 0402_Dup1: P/N: 151B10400S
C64 C68 = 10uF,6.3V,0603,20%X5R_Dup1: P/N: 151C10610S
C66 = 1uF,X5R,6.3V,0402: P/N: 151D10510S
C67 = 100nF, 10V, X7R, 10%, 0402: P/N: 151C22400S
D3 = BAT54WS_0: P/N: 130E05402S
L6 L7 L9-L11 = ESD_CHOKE_DIFFx2_10: P/N: 142D11801S
L8 = INC DELTA SI43-100, 10uH: P/N: 147A10001S; CLABCONF1: <null>
P7 = FPC_40_05mm: P/N: 182P04001S
P8 = FPC_Connector_6: P/N: 182P00803S
R85 = 10K,1%,0402,1/16W_0_Dup1: P/N: 161C10021S; CLABCONF0: DNP
R86 R87 R89 = 0R, 1206: P/N: 161F00005S
R88 = 10K,1%,0402,1/16W_0_Dup1: P/N: 161C10021S
R90 = 2.2R,5%,0402,1/16W: P/N: 161C06R25S; CLABCONF0: DNP
R91 = 2.2R,5%,0402,1/16W: P/N: 161C0R751S
R92 R94 R98 R100 = 10K,1%,0402,1/16W: P/N: 161C10021S
R93 R95 R97 R99 = 10K,1%,0402,1/16W: P/N: 161C10021S; CLABCONF0: DNP
R96 = 2.2R,5%,0402,1/16W: P/N: 161C00005S
TP6 = TESTPOINT: CLABCONF0: DNP
U5 = TPS61165DBVT: P/N: 123C15100S
U6 = IP4220CZ6_0: P/N: 132D42200S

## Sheet 09 MIPI-CSI Camera Conn.SchDoc
size 420 x 297 mm; DocumentNumber: 9; SheetNumber: 9; SheetTotal: 12
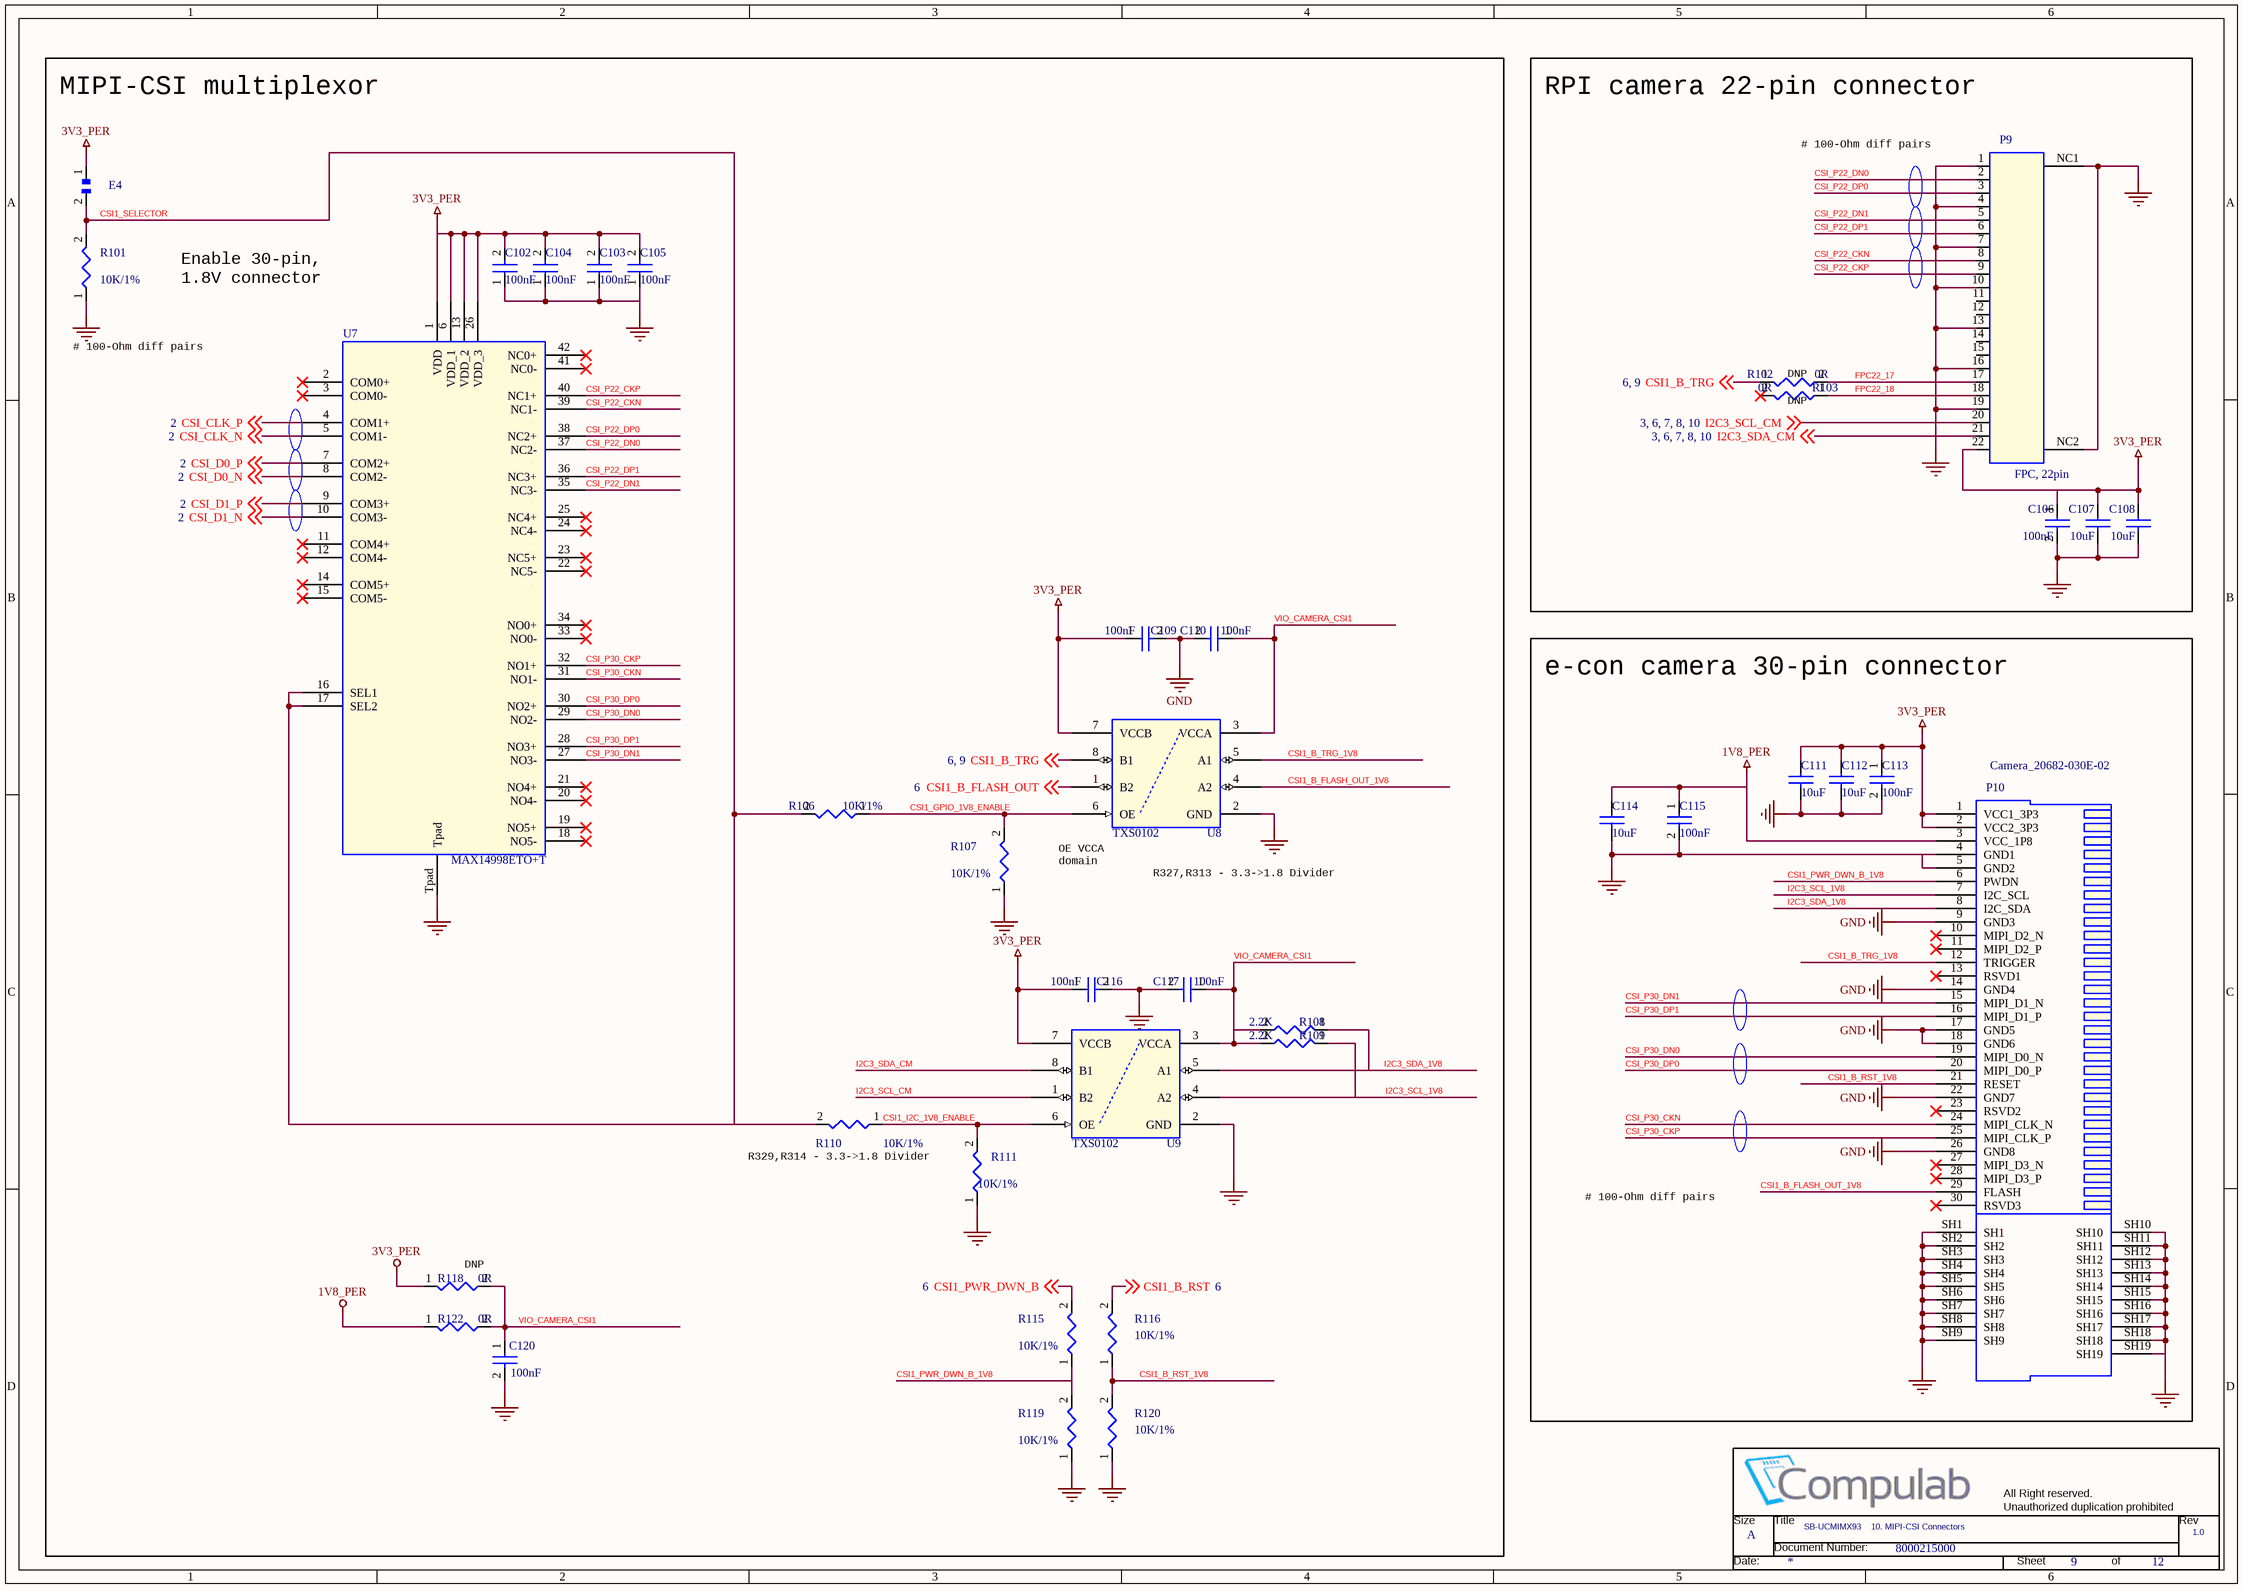
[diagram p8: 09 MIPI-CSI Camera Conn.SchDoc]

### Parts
(Parts that share a designator on the sheet are numbered #1, #2 ... from top to bottom, then left to right.)
*#10  Title: SB-UCMIMX93    10. MIPI-CSI Connectors  Doc: 8000215000  RevCode: 1.0  Page Size: A  Page Number: 9  Page Count: 12  (hidden comment: CompuLabTitleBlk)  (graphical)
C102  100nF  [RC0402]
C103  100nF  [RC0402]
C104  100nF  [RC0402]
C105  100nF  [RC0402]
C106  100nF  [RC0402]
C107  10uF  [RC0603]
C108  10uF  [RC0603]
C109  100nF  [RC0402]
C110  100nF  [RC0402]
C111  10uF  [RC0603]
C112  10uF  [RC0603]
C113  100nF  [RC0402]
C114  10uF  [RC0603]
C115  100nF  [RC0402]
C116  100nF  [RC0402]
C117  100nF  [RC0402]
C120  100nF  [RC0402]
E4  HDR1X2  [1X2THHDR]  (value not drawn)
P9  FPC, 22pin  [FPC05SM22]
P10  Camera_20682-030E-02  [CON30]
R101  10K/1%  [RC0402]
R102  0R  [RC0402]
R103  0R  [RC0402]
R106  10K/1%  [RC0402]
R107  10K/1%  [RC0402]
R108  2.2K  [RC0402]
R109  2.2K  [RC0402]
R110  10K/1%  [RC0402]
R111  10K/1%  [RC0402]
R115  10K/1%  [RC0402]
R116  10K/1%  [RC0402]
R118  0R  [RC0402]
R119  10K/1%  [RC0402]
R120  10K/1%  [RC0402]
R122  0R  [RC0402]
U7  < Value >: MAX14998ETO+T  [21-0181B_T423590M-1_MXM]
U8  TXS0102  [MO-187DA-8]
U9  TXS0102  [MO-187DA-8]

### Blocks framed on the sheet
MIPI-CSI multiplexor: C102-C105 C109 C110 C116 C117 C120 E4 R101 R106-R111 R115 R116 R118-R120 R122 U7-U9
RPI camera 22-pin connector: C106-C108 P9 R102 R103
e-con camera 30-pin connector: C111-C115 P10

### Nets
1V8_PER: C114.1 C115.1 P10.3(VCC_1P8) R122.1
3V3_PER: C102.2 C103.2 C104.2 C105.2 C106.1 C107.1 C108.1 C109.1 C111.1 C112.1 C113.1 C116.1 E4.1 P9.22 P10.1(VCC1_3P3) P10.2(VCC2_3P3) R118.1 U7.1(VDD) U7.6(VDD_1) U7.13(VDD_2) U7.26(VDD_3) U8.7(VCCB) U9.7(VCCB)
GND: C102.1 C103.1 C104.1 C105.1 C106.2 C107.2 C108.2 C109.2 C110.2 C111.2 C112.2 C113.2 C114.2 C115.2 C116.2 C117.2 C120.2 P9.1 P9.4 P9.7 P9.10 P9.13 P9.16 P9.19 P9.NC1 P9.NC2 P10.4(GND1) P10.5(GND2) P10.9(GND3) P10.14(GND4) P10.17(GND5) P10.18(GND6) P10.22(GND7) P10.26(GND8) P10.SH1 P10.SH2 P10.SH3 P10.SH4 P10.SH5 P10.SH6 P10.SH7 P10.SH8 P10.SH9 P10.SH10 P10.SH11 P10.SH12 P10.SH13 P10.SH14 P10.SH15 P10.SH16 P10.SH17 P10.SH18 P10.SH19 R101.1 R107.1 R111.1 R119.1 R120.1 U7.Tpad U8.2(GND) U9.2(GND)
CSI1_B_FLASH_OUT: U8.1(B2) ; off-sheet CSI1_B_FLASH_OUT
CSI1_B_FLASH_OUT_1V8: P10.29(FLASH) U8.4(A2)
CSI1_B_RST: R116.2 ; off-sheet CSI1_B_RST
CSI1_B_RST_1V8: P10.21(RESET) R116.1 R120.2
CSI1_B_TRG: R102.1 U8.8(B1) ; off-sheet CSI1_B_TRG
CSI1_B_TRG_1V8: P10.12(TRIGGER) U8.5(A1)
CSI1_GPIO_1V8_ENABLE: R106.1 R107.2 U8.6(OE)
CSI1_I2C_1V8_ENABLE: R110.1 R111.2 U9.6(OE)
CSI1_PWR_DWN_B: R115.2 ; off-sheet CSI1_PWR_DWN_B
CSI1_PWR_DWN_B_1V8: P10.6(PWDN) R115.1 R119.2
CSI1_SELECTOR: E4.2 R101.2 R106.2 R110.2 U7.16(SEL1) U7.17(SEL2)
CSI_CLK_N: U7.5(COM1-) ; off-sheet CSI_CLK_N
CSI_CLK_P: U7.4(COM1+) ; off-sheet CSI_CLK_P
CSI_D0_N: U7.8(COM2-) ; off-sheet CSI_D0_N
CSI_D0_P: U7.7(COM2+) ; off-sheet CSI_D0_P
CSI_D1_N: U7.10(COM3-) ; off-sheet CSI_D1_N
CSI_D1_P: U7.9(COM3+) ; off-sheet CSI_D1_P
CSI_P22_CKN: P9.8 U7.39(NC1-)
CSI_P22_CKP: P9.9 U7.40(NC1+)
CSI_P22_DN0: P9.2 U7.37(NC2-)
CSI_P22_DN1: P9.5 U7.35(NC3-)
CSI_P22_DP0: P9.3 U7.38(NC2+)
CSI_P22_DP1: P9.6 U7.36(NC3+)
CSI_P30_CKN: P10.24(MIPI_CLK_N) U7.31(NO1-)
CSI_P30_CKP: P10.25(MIPI_CLK_P) U7.32(NO1+)
CSI_P30_DN0: P10.19(MIPI_D0_N) U7.29(NO2-)
CSI_P30_DN1: P10.15(MIPI_D1_N) U7.27(NO3-)
CSI_P30_DP0: P10.20(MIPI_D0_P) U7.30(NO2+)
CSI_P30_DP1: P10.16(MIPI_D1_P) U7.28(NO3+)
FPC22_17: P9.17 R102.2
FPC22_18: P9.18 R103.1
I2C3_SCL_1V8: P10.7(I2C_SCL) R109.1 U9.4(A2)
I2C3_SCL_CM: P9.20 U9.1(B2) ; off-sheet I2C3_SCL_CM
I2C3_SDA_1V8: P10.8(I2C_SDA) R108.1 U9.5(A1)
I2C3_SDA_CM: P9.21 U9.8(B1) ; off-sheet I2C3_SDA_CM
VIO_CAMERA_CSI1: C110.1 C117.1 C120.1 R108.2 R109.2 R118.2 R122.2 U8.3(VCCA) U9.3(VCCA)

Not connected (* = marked no-connect by the designer): P9 11 12 14 15; P10 10(MIPI_D2_N)* 11(MIPI_D2_P)* 13(RSVD1)* 23(RSVD2)* 27(MIPI_D3_N)* 28(MIPI_D3_P)* 30(RSVD3)*; R103 2*; U7 2(COM0+)* 3(COM0-)* 11(COM4+)* 12(COM4-)* 14(COM5+)* 15(COM5-)* 18(NO5-)* 19(NO5+)* 20(NO4-)* 21(NO4+)* 22(NC5-)* 23(NC5+)* 24(NC4-)* 25(NC4+)* 33(NO0-)* 34(NO0+)* 41(NC0-)* 42(NC0+)*

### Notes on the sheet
- # 100-Ohm diff pairs
- Enable 30-pin,
  1.8V connector
- (near R102) DNP
- (near R103) DNP
- (near U8) OE VCCA
  domain
- R327,R313 - 3.3->1.8 Divider
- (near R110) R329,R314 - 3.3->1.8 Divider
- (near R118) DNP

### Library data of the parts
C102-C105 C109 C110 C116 C117 C120 = 100nF, 10V, X7R, 10%, 0402_Dup1: P/N: 151B10400S
C106 C113 C115 = 100nF, 10V, X7R, 10%, 0402: P/N: 151B10400S
C107 C108 C111 C112 C114 = 10uF,6_0.3V,0603,20%X5R: P/N: 151B10610S
E4 = HDR 1x2 100MIL TH JUMPER: P/N: 190C00200
P9 = FPC, 0.5mm, 22 cont_0.: P/N: 182P02201S
P10 = Camera_20682-030E-02: P/N: 182K03002S
R101 R106 R107 R110 R111 R115 R116 R119 R120 = 10K,1%,0402,1/16W: P/N: 161C10021S
R102 R118 = 0R, 0402_0: P/N: 161C00005S; CLABCONF0: DNP
R103 = 0R, 0402_1: P/N: 161C00005S; CLABCONF0: DNP
R108 R109 = 2.2K,5%,0402.1/16W: P/N: 161C22015S
R122 = 0R, 0402_0: P/N: 161C00005S
U7 = MAX14998ETOT: P/N: 124S10070S; IsHeterogeneous: False; DevicesInView: 1; DeviceDesignator: A; DeviceNumbering: Alpha; OriginalSymbolOrigin: (30000,10000)
U8 U9 = TXS0102_0: P/N: 116A01020S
